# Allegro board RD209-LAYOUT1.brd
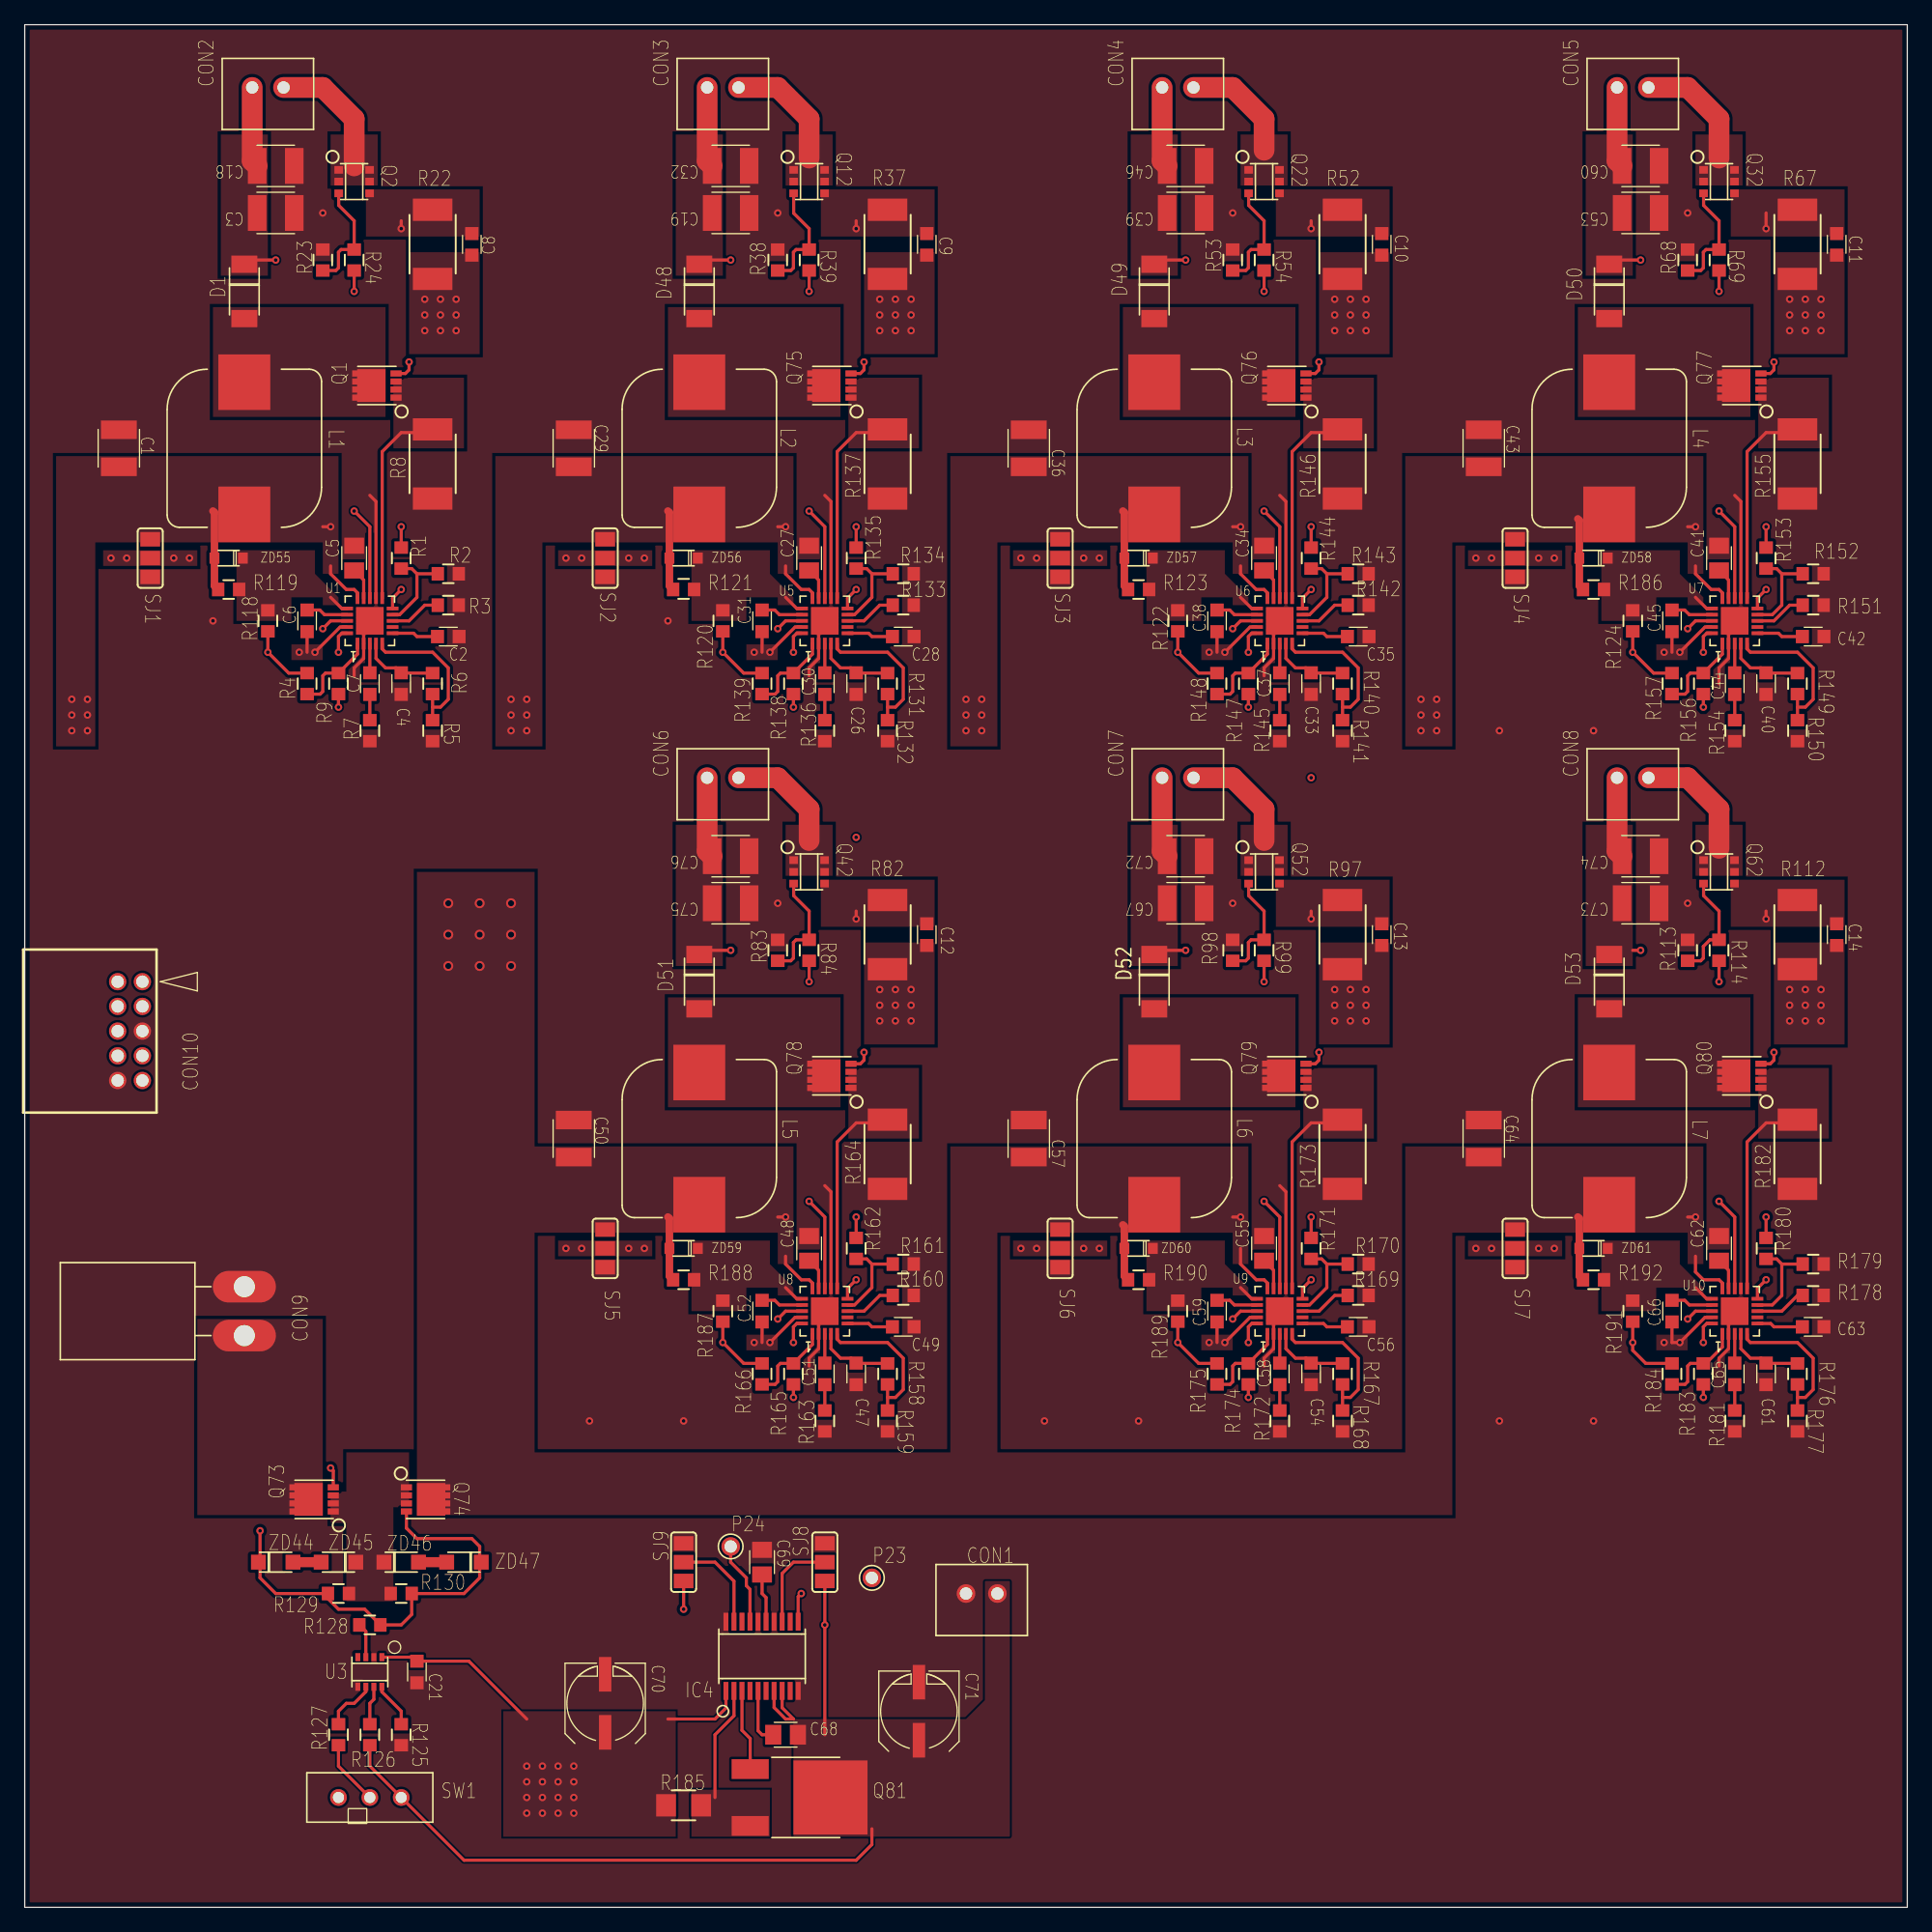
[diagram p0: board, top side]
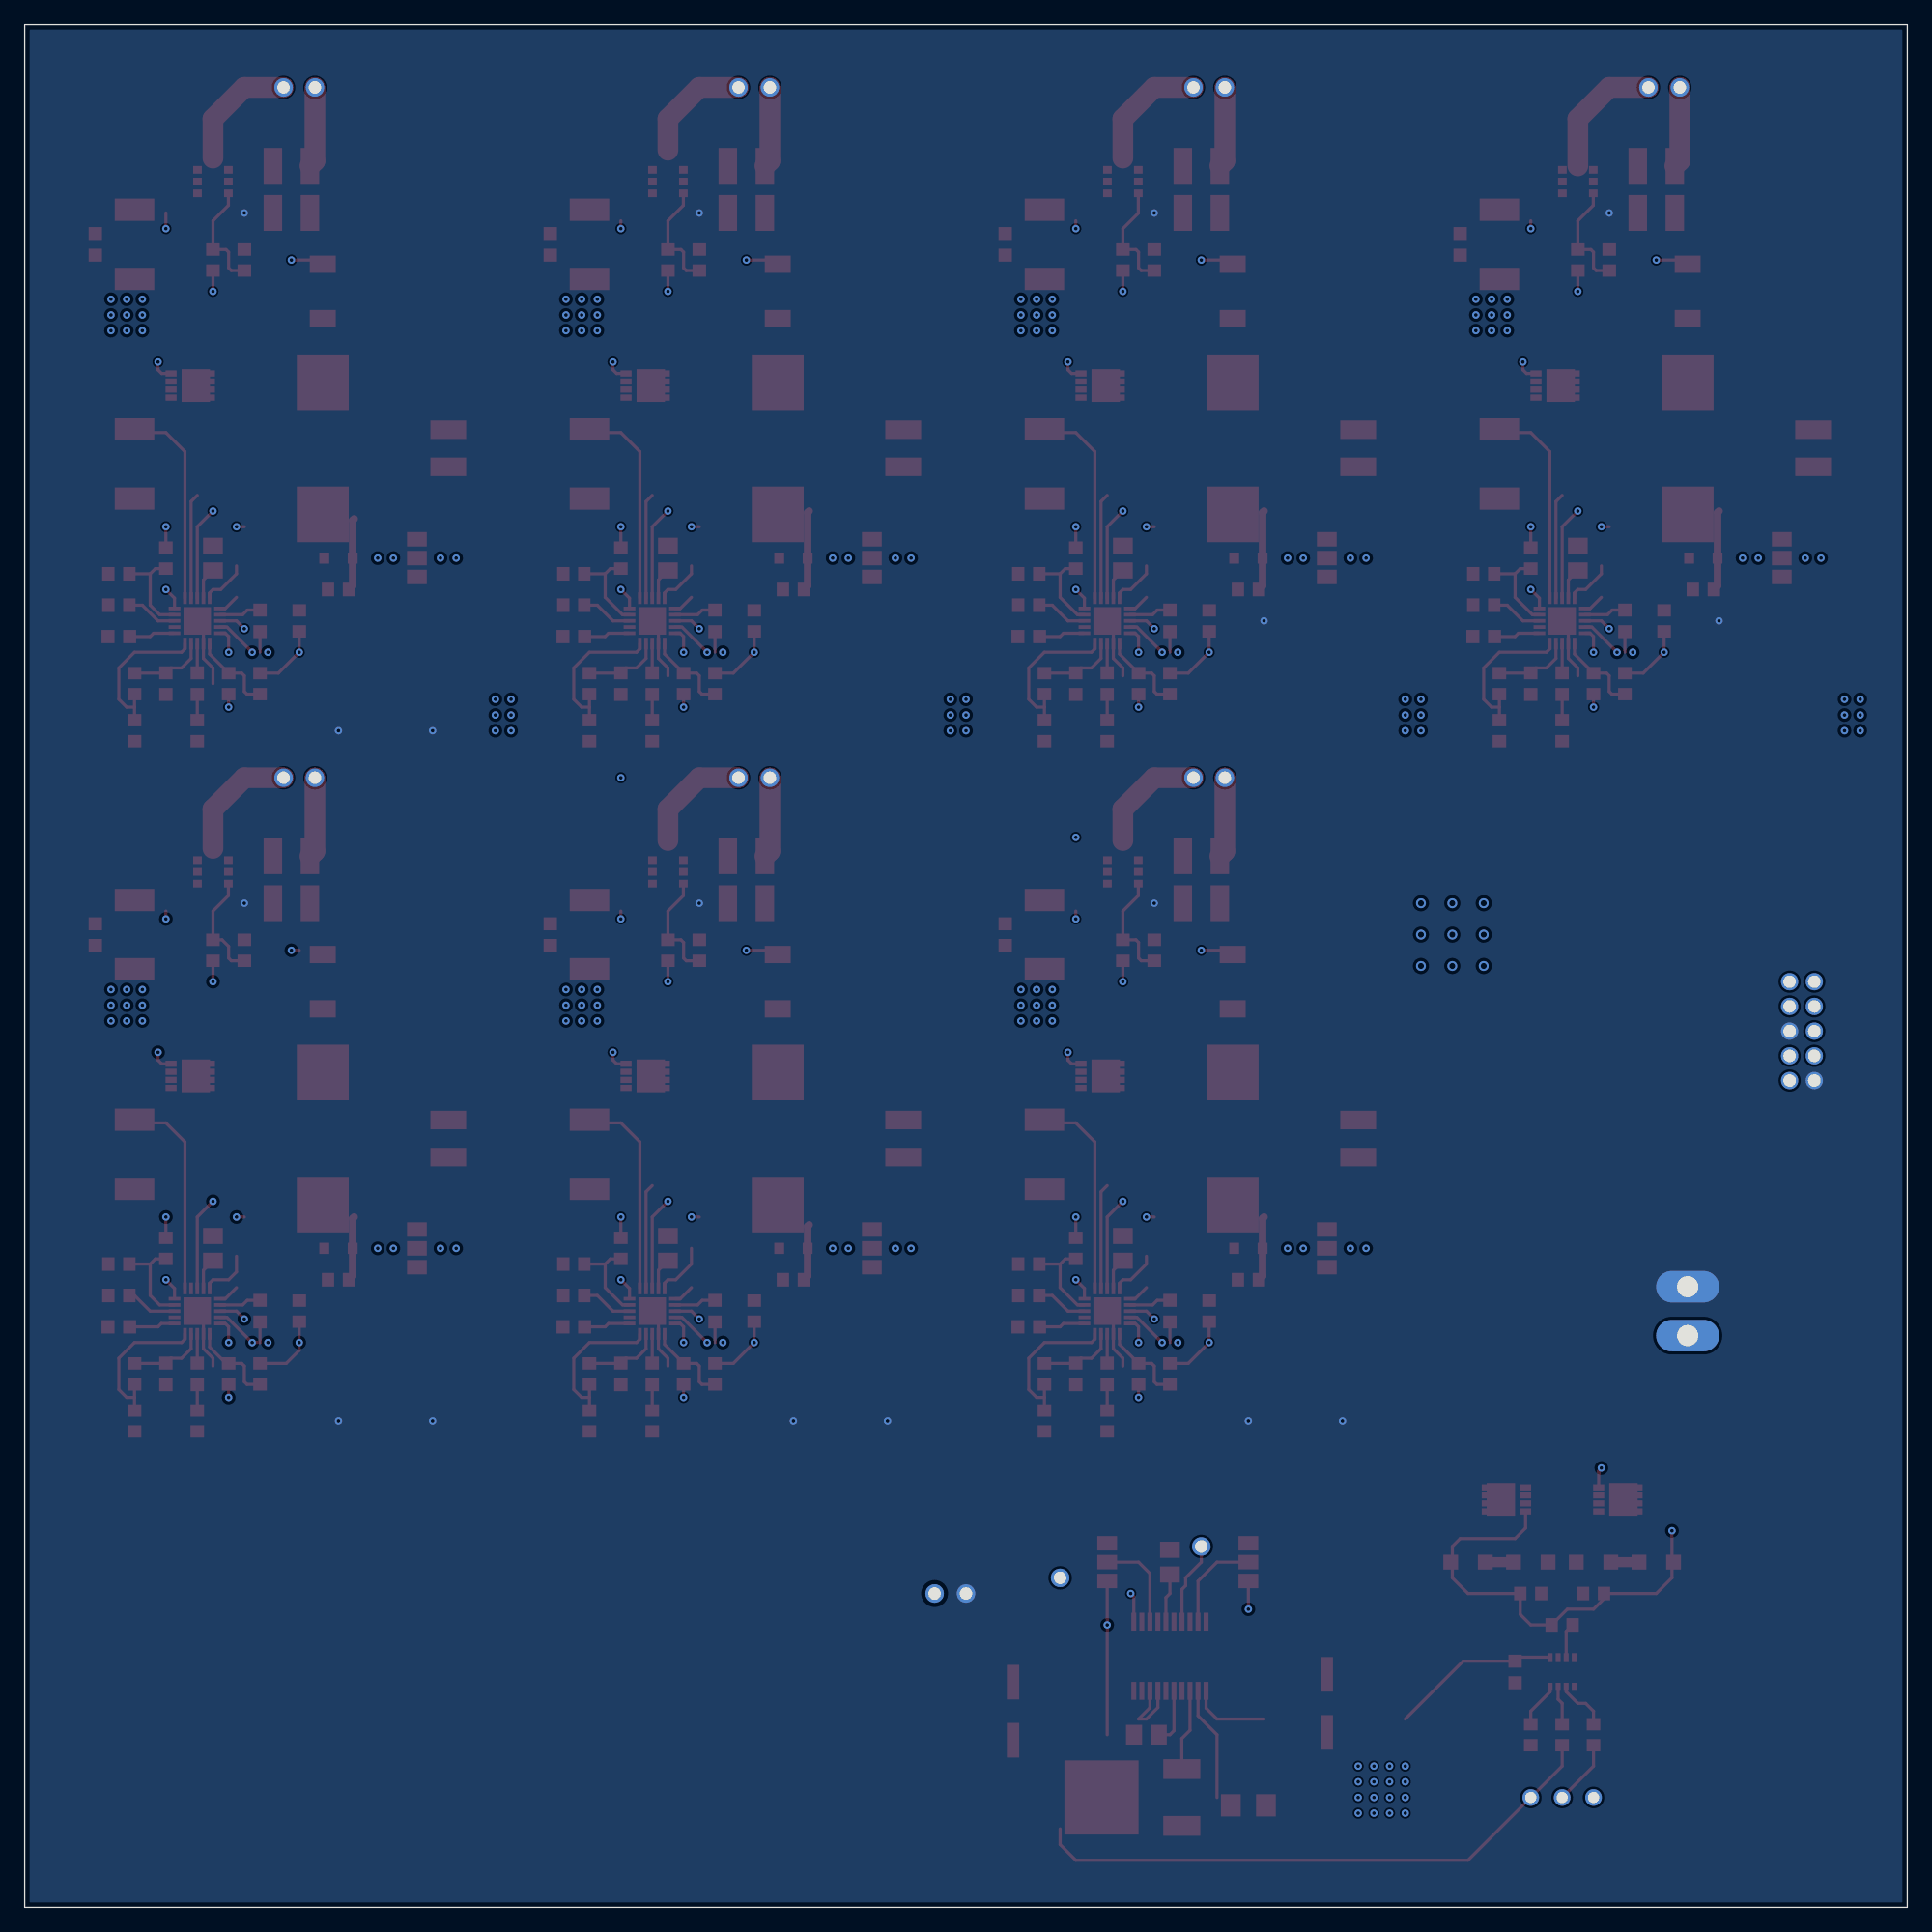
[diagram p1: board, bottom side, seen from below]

Outline 152.4 x 152.4 mm; copper layers: TOP, CONDUCTIVE2, CONDUCTIVE3, BOTTOM. Coordinates in mm from the lower left corner of the outline.
Outline path: rectangle 0,0 152.4,152.4

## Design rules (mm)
constraint set DEFAULT: 

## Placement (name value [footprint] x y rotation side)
C1  -  [C1210K]  7.62 118.11 270 top
C2  -  [C0603K]  34.29 102.87 180 top
C3  -  [C1210K]  20.32 137.16 180 top
C4  -  [C0603K]  30.48 99.06 90 top
C5  -  [C0805K]  26.67 109.22 270 top
C6  -  [C0603K]  22.86 104.14 90 top
C7  -  [C0603K]  27.94 99.06 90 top
C8  -  [C0603K]  36.2 134.62 90 top
C9  -  [C0603K]  73.02 134.62 90 top
C10  -  [C0603K]  109.85 134.62 90 top
C11  -  [C0603K]  146.69 134.62 90 top
C12  -  [C0603K]  73.02 78.74 90 top
C13  -  [C0603K]  109.85 78.74 90 top
C14  -  [C0603K]  146.69 78.74 90 top
C18  -  [C1210K]  20.32 140.97 180 top
C19  -  [C1210K]  57.15 137.16 180 top
C21  -  [C0603K]  31.75 19.05 270 top
C26  -  [C0603K]  67.31 99.06 90 top
C27  -  [C0805K]  63.5 109.22 270 top
C28  -  [C0603K]  71.12 102.87 180 top
C29  -  [C1210K]  44.45 118.11 270 top
C30  -  [C0603K]  64.77 99.06 90 top
C31  -  [C0603K]  59.69 104.14 90 top
C32  -  [C1210K]  57.15 140.97 180 top
C33  -  [C0603K]  104.14 99.06 90 top
C34  -  [C0805K]  100.33 109.22 270 top
C35  -  [C0603K]  107.95 102.87 180 top
C36  -  [C1210K]  81.28 118.11 270 top
C37  -  [C0603K]  101.6 99.06 90 top
C38  -  [C0603K]  96.52 104.14 90 top
C39  -  [C1210K]  93.98 137.16 180 top
C40  -  [C0603K]  140.97 99.06 90 top
C41  -  [C0805K]  137.16 109.22 270 top
C42  -  [C0603K]  144.78 102.87 180 top
C43  -  [C1210K]  118.11 118.11 270 top
C44  -  [C0603K]  138.43 99.06 90 top
C45  -  [C0603K]  133.35 104.14 90 top
C46  -  [C1210K]  93.98 140.97 180 top
C47  -  [C0603K]  67.31 43.18 90 top
C48  -  [C0805K]  63.5 53.34 270 top
C49  -  [C0603K]  71.12 46.99 180 top
C50  -  [C1210K]  44.45 62.23 270 top
C51  -  [C0603K]  64.77 43.18 90 top
C52  -  [C0603K]  59.69 48.26 90 top
C53  -  [C1210K]  130.81 137.16 180 top
C54  -  [C0603K]  104.14 43.18 90 top
C55  -  [C0805K]  100.33 53.34 270 top
C56  -  [C0603K]  107.95 46.99 180 top
C57  -  [C1210K]  81.28 62.23 270 top
C58  -  [C0603K]  101.6 43.18 90 top
C59  -  [C0603K]  96.52 48.26 90 top
C60  -  [C1210K]  130.81 140.97 180 top
C61  -  [C0603K]  140.97 43.18 90 top
C62  -  [C0805K]  137.16 53.34 270 top
C63  -  [C0603K]  144.78 46.99 180 top
C64  -  [C1210K]  118.11 62.23 270 top
C65  -  [C0603K]  138.43 43.18 90 top
C66  -  [C0603K]  133.35 48.26 90 top
C67  -  [C1210K]  93.98 81.28 180 top
C68  -  [C0805K]  61.6 13.97 180 top
C69  -  [C0805K]  59.69 27.94 90 top
C70  -  [UD_6_3X5_8_NICHICON]  46.99 16.51 270 top
C71  -  [UD_6_3X5_8_NICHICON]  72.39 15.88 270 top
C72  -  [C1210K]  93.98 85.09 180 top
C73  -  [C1210K]  130.81 81.28 180 top
C74  -  [C1210K]  130.81 85.09 180 top
C75  -  [C1210K]  57.15 81.28 180 top
C76  -  [C1210K]  57.15 85.09 180 top
CON1  -  [B2B_XH_A]  77.47 25.4 180 top
CON2  -  [B2B_XH_A]  19.68 147.32 180 top
CON3  -  [B2B_XH_A]  56.52 147.32 180 top
CON4  -  [B2B_XH_A]  93.34 147.32 180 top
CON5  -  [B2B_XH_A]  130.18 147.32 180 top
CON6  -  [B2B_XH_A]  56.52 91.44 180 top
CON7  -  [B2B_XH_A]  93.34 91.44 180 top
CON8  -  [B2B_XH_A]  130.18 91.44 180 top
CON9  -  [B2PS_VH]  17.78 48.26 90 top
CON10  -  [CTK03280ATP]  9.53 74.93 270 top
D1  -  [M_FLAT]  17.78 130.81 90 top
D48  -  [M_FLAT]  54.61 130.81 90 top
D49  -  [M_FLAT]  91.44 130.81 90 top
D50  -  [M_FLAT]  128.27 130.81 90 top
D51  -  [M_FLAT]  54.61 74.93 90 top
D52  -  [M_FLAT]  91.44 74.93 90 top
D53  -  [M_FLAT]  128.27 74.93 90 top
IC4  -  [TB9005FNG]  59.69 20.32 0 top
L1  -  [CLF12577NI_D]  17.78 118.11 90 top
L2  -  [CLF12577NI_D]  54.61 118.11 90 top
L3  -  [CLF12577NI_D]  91.44 118.11 90 top
L4  -  [CLF12577NI_D]  128.27 118.11 90 top
L5  -  [CLF12577NI_D]  54.61 62.23 90 top
L6  -  [CLF12577NI_D]  91.44 62.23 90 top
L7  -  [CLF12577NI_D]  128.27 62.23 90 top
P23  -  [CT]  68.58 26.67 270 top
P24  -  [CT]  57.15 29.21 270 top
Q1  -  [TSON_ADVANCE_WF_]  29.21 123.19 90 top
Q2  -  [TSOP6F]  26.67 139.7 270 top
Q12  -  [TSOP6F]  63.5 139.7 270 top
Q22  -  [TSOP6F]  100.33 139.7 270 top
Q32  -  [TSOP6F]  137.16 139.7 270 top
Q42  -  [TSOP6F]  63.5 83.82 270 top
Q52  -  [TSOP6F]  100.33 83.82 270 top
Q62  -  [TSOP6F]  137.16 83.82 270 top
Q73  -  [TSON_ADVANCE_WF_]  24.13 33.02 90 top
Q74  -  [TSON_ADVANCE_WF_]  31.75 33.02 270 top
Q75  -  [TSON_ADVANCE_WF_]  66.04 123.19 90 top
Q76  -  [TSON_ADVANCE_WF_]  102.87 123.19 90 top
Q77  -  [TSON_ADVANCE_WF_]  139.7 123.19 90 top
Q78  -  [TSON_ADVANCE_WF_]  66.04 67.31 90 top
Q79  -  [TSON_ADVANCE_WF_]  102.87 67.31 90 top
Q80  -  [TSON_ADVANCE_WF_]  139.7 67.31 90 top
Q81  -  [TTA005]  62.23 8.89 270 top
R1  -  [R0603]  30.48 109.22 90 top
R2  -  [R0603]  34.29 107.95 180 top
R3  -  [R0603]  34.29 105.41 0 top
R4  -  [R0603]  22.86 99.06 90 top
R5  -  [R0603]  33.02 95.25 270 top
R6  -  [R0603]  33.02 99.06 90 top
R7  -  [R0603]  27.94 95.25 90 top
R8  -  [R2512]  33.02 116.84 90 top
R9  -  [R0603]  25.4 99.06 90 top
R22  -  [R2512]  33.02 134.62 90 top
R23  -  [R0603]  24.13 133.35 270 top
R24  -  [R0603]  26.67 133.35 270 top
R37  -  [R2512]  69.85 134.62 90 top
R38  -  [R0603]  60.96 133.35 270 top
R39  -  [R0603]  63.5 133.35 270 top
R52  -  [R2512]  106.68 134.62 90 top
R53  -  [R0603]  97.79 133.35 270 top
R54  -  [R0603]  100.33 133.35 270 top
R67  -  [R2512]  143.51 134.62 90 top
R68  -  [R0603]  134.62 133.35 270 top
R69  -  [R0603]  137.16 133.35 270 top
R82  -  [R2512]  69.85 78.74 90 top
R83  -  [R0603]  60.96 77.47 270 top
R84  -  [R0603]  63.5 77.47 270 top
R97  -  [R2512]  106.68 78.74 90 top
R98  -  [R0603]  97.79 77.47 270 top
R99  -  [R0603]  100.33 77.47 270 top
R112  -  [R2512]  143.51 78.74 90 top
R113  -  [R0603]  134.62 77.47 270 top
R114  -  [R0603]  137.16 77.47 270 top
R118  -  [R0603]  19.68 104.14 270 top
R119  -  [R0603]  16.51 106.68 180 top
R120  -  [R0603]  56.52 104.14 270 top
R121  -  [R0603]  53.34 106.68 180 top
R122  -  [R0603]  93.34 104.14 270 top
R123  -  [R0603]  90.17 106.68 180 top
R124  -  [R0603]  130.18 104.14 270 top
R125  -  [R0603]  30.48 13.97 90 top
R126  -  [R0603]  27.94 13.97 270 top
R127  -  [R0603]  25.4 13.97 90 top
R128  -  [R0603]  27.94 22.86 0 top
R129  -  [R0603]  25.4 25.4 180 top
R130  -  [R0603]  30.48 25.4 180 top
R131  -  [R0603]  69.85 99.06 90 top
R132  -  [R0603]  69.85 95.25 270 top
R133  -  [R0603]  71.12 105.41 0 top
R134  -  [R0603]  71.12 107.95 180 top
R135  -  [R0603]  67.31 109.22 90 top
R136  -  [R0603]  64.77 95.25 90 top
R137  -  [R2512]  69.85 116.84 90 top
R138  -  [R0603]  62.23 99.06 90 top
R139  -  [R0603]  59.69 99.06 90 top
R140  -  [R0603]  106.68 99.06 90 top
R141  -  [R0603]  106.68 95.25 270 top
R142  -  [R0603]  107.95 105.41 0 top
R143  -  [R0603]  107.95 107.95 180 top
R144  -  [R0603]  104.14 109.22 90 top
R145  -  [R0603]  101.6 95.25 90 top
R146  -  [R2512]  106.68 116.84 90 top
R147  -  [R0603]  99.06 99.06 90 top
R148  -  [R0603]  96.52 99.06 90 top
R149  -  [R0603]  143.51 99.06 90 top
R150  -  [R0603]  143.51 95.25 270 top
R151  -  [R0603]  144.78 105.41 0 top
R152  -  [R0603]  144.78 107.95 180 top
R153  -  [R0603]  140.97 109.22 90 top
R154  -  [R0603]  138.43 95.25 90 top
R155  -  [R2512]  143.51 116.84 90 top
R156  -  [R0603]  135.89 99.06 90 top
R157  -  [R0603]  133.35 99.06 90 top
R158  -  [R0603]  69.85 43.18 90 top
R159  -  [R0603]  69.85 39.37 270 top
R160  -  [R0603]  71.12 49.53 0 top
R161  -  [R0603]  71.12 52.07 180 top
R162  -  [R0603]  67.31 53.34 90 top
R163  -  [R0603]  64.77 39.37 90 top
R164  -  [R2512]  69.85 60.96 90 top
R165  -  [R0603]  62.23 43.18 90 top
R166  -  [R0603]  59.69 43.18 90 top
R167  -  [R0603]  106.68 43.18 90 top
R168  -  [R0603]  106.68 39.37 270 top
R169  -  [R0603]  107.95 49.53 0 top
R170  -  [R0603]  107.95 52.07 180 top
R171  -  [R0603]  104.14 53.34 90 top
R172  -  [R0603]  101.6 39.37 90 top
R173  -  [R2512]  106.68 60.96 90 top
R174  -  [R0603]  99.06 43.18 90 top
R175  -  [R0603]  96.52 43.18 90 top
R176  -  [R0603]  143.51 43.18 90 top
R177  -  [R0603]  143.51 39.37 270 top
R178  -  [R0603]  144.78 49.53 0 top
R179  -  [R0603]  144.78 52.07 180 top
R180  -  [R0603]  140.97 53.34 90 top
R181  -  [R0603]  138.43 39.37 90 top
R182  -  [R2512]  143.51 60.96 90 top
R183  -  [R0603]  135.89 43.18 90 top
R184  -  [R0603]  133.35 43.18 90 top
R185  -  [R1206]  53.34 8.26 0 top
R186  -  [R0603]  127 106.68 180 top
R187  -  [R0603]  56.52 48.26 270 top
R188  -  [R0603]  53.34 50.8 180 top
R189  -  [R0603]  93.34 48.26 270 top
R190  -  [R0603]  90.17 50.8 180 top
R191  -  [R0603]  130.18 48.26 270 top
R192  -  [R0603]  127 50.8 180 top
SJ1  -  [SJ_2]  10.16 109.22 90 top
SJ2  -  [SJ_2]  46.99 109.22 90 top
SJ3  -  [SJ_2]  83.82 109.22 90 top
SJ4  -  [SJ_2]  120.65 109.22 90 top
SJ5  -  [SJ_2]  46.99 53.34 90 top
SJ6  -  [SJ_2]  83.82 53.34 90 top
SJ7  -  [SJ_2]  120.65 53.34 90 top
SJ8  -  [SJ_2]  64.77 27.94 90 top
SJ9  -  [SJ_2]  53.34 27.94 90 top
SW1  -  [SS_12SDP2]  27.94 8.89 90 top
U1  -  [20_TQFN]  27.94 104.14 0 top
U3  -  [PS_8]  27.94 19.05 180 top
U5  -  [20_TQFN]  64.77 104.14 0 top
U6  -  [20_TQFN]  101.6 104.14 0 top
U7  -  [20_TQFN]  138.43 104.14 0 top
U8  -  [20_TQFN]  64.77 48.26 0 top
U9  -  [20_TQFN]  101.6 48.26 0 top
U10  -  [20_TQFN]  138.43 48.26 0 top
ZD44  -  [ZD_16V]  20.32 27.94 180 top
ZD45  -  [ZD_16V]  25.4 27.94 0 top
ZD46  -  [ZD_16V]  30.48 27.94 180 top
ZD47  -  [ZD_16V]  35.56 27.94 0 top
ZD55  -  [USC]  16.51 109.22 180 top
ZD56  -  [USC]  53.34 109.22 180 top
ZD57  -  [USC]  90.17 109.22 180 top
ZD58  -  [USC]  127 109.22 180 top
ZD59  -  [USC]  53.34 53.34 180 top
ZD60  -  [USC]  90.17 53.34 180 top
ZD61  -  [USC]  127 53.34 180 top

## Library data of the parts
C1 C3 C18 C19 C29 C32 C36 C39 C43 C46 C50 C53 C57 C60 C64 C67 C72-C76 = C1210K: alternate symbols: (T:C1210K;B:C1210K_bk)
C2 C28 C35 C42 C49 C56 C63 = C0603K_1: alternate symbols: (T:C0603K;B:C0603K_bk)
C4 C6 C26 C31 C33 C38 C40 C45 C47 C52 C54 C59 C61 C66 = C0603K_3: alternate symbols: (T:C0603K;B:C0603K_bk)
C5 C27 C34 C41 C48 C55 C62 = C0805K_1: alternate symbols: (T:C0805K;B:C0805K_bk)
C7 C30 C37 C44 C51 C58 C65 = C0603K_4: alternate symbols: (T:C0603K;B:C0603K_bk)
C8-C14 = C0603K: alternate symbols: (T:C0603K;B:C0603K_bk)
C21 = C0603K_2: alternate symbols: (T:C0603K;B:C0603K_bk)
C68 = C0805K_2: alternate symbols: (T:C0805K;B:C0805K_bk)
C69 = C0805K_3: alternate symbols: (T:C0805K;B:C0805K_bk)
C70 C71 = UD-6_3X5_8_NICHICON: alternate symbols: (T:UD_6_3X5_8_NICHICON;B:UD_6_3X5_8_NICHICON__1)
CON1-CON8 = B2B-XH-A: alternate symbols: (T:B2B_XH_A;B:B2B_XH_A_bk)
CON9 = B2PS-VH: alternate symbols: (T:B2PS_VH;B:B2PS_VH_bk)
CON10 = GDM220002192: alternate symbols: (T:CTK03280ATP;B:CTK03280BTP)
D1 D48-D53 = M-FLAT: alternate symbols: (T:M_FLAT;B:M_FLAT_bk)
IC4 = TB9005FNG: alternate symbols: (T:TB9005FNG;B:TB9005FNG_bk)
L1-L7 = CLF12577NI-D: alternate symbols: (T:CLF12577NI_D;B:CLF12577NI_D_bk)
P23 P24 = CT: alternate symbols: (T:CT;B:CT_bk)
Q1 Q75-Q80 = TSON_ADVANCE_WF_1: alternate symbols: (T:TSON_ADVANCE_WF_;B:TSON_ADVANCE_WF_bk)
Q2 Q12 Q22 Q32 Q42 Q52 Q62 = TSOP6F: alternate symbols: (T:TSOP6F;B:TSOP6F_bk)
Q73 Q74 = TSON_ADVANCE_WF_2: alternate symbols: (T:TSON_ADVANCE_WF_;B:TSON_ADVANCE_WF_bk)
Q81 = TTA005: alternate symbols: (T:TTA005;B:TTA005_bk)
R1 R135 R144 R153 R162 R171 R180 = R0603_1: alternate symbols: (T:R0603;B:R0603_bk)
R2 R9 R126 R127 R134 R138 R143 R147 R152 R156 R161 R165 R170 R174 R179 R183 = R0603_6: alternate symbols: (T:R0603;B:R0603_bk)
R3 R133 R142 R151 R160 R169 R178 = R0603_8: alternate symbols: (T:R0603;B:R0603_bk)
R4 R139 R148 R157 R166 R175 R184 = R0603_9: alternate symbols: (T:R0603;B:R0603_bk)
R5 R132 R141 R150 R159 R168 R177 = R0603_10: alternate symbols: (T:R0603;B:R0603_bk)
R6 R131 R140 R149 R158 R167 R176 = R0603_11: alternate symbols: (T:R0603;B:R0603_bk)
R7 R136 R145 R154 R163 R172 R181 = R0603_12: alternate symbols: (T:R0603;B:R0603_bk)
R8 R22 R37 R52 R67 R82 R97 R112 R137 R146 R155 R164 R173 R182 = R2512: alternate symbols: (T:R2512;B:R2512_bk)
R23 R38 R53 R68 R83 R98 R113 R119 R121 R123 R186 R188 R190 R192 = R0603: alternate symbols: (T:R0603;B:R0603_bk)
R24 R39 R54 R69 R84 R99 R114 = R0603_7: alternate symbols: (T:R0603;B:R0603_bk)
R118 R120 R122 R124 R187 R189 R191 = R0603_2: alternate symbols: (T:R0603;B:R0603_bk)
R125 = R0603_3: alternate symbols: (T:R0603;B:R0603_bk)
R128 = R0603_4: alternate symbols: (T:R0603;B:R0603_bk)
R129 R130 = R0603_5: alternate symbols: (T:R0603;B:R0603_bk)
R185 = R1206: alternate symbols: (T:R1206;B:R1206_bk)
SJ1-SJ9 = SJ_2: alternate symbols: (T:SJ_2;B:SJ_2_bk)
SW1 = SS-12SDP2: alternate symbols: (T:SS_12SDP2;B:SS_12SDP2_bk)
U1 U5-U10 = 20-TQFN: alternate symbols: (T:20_TQFN;B:20_TQFN_bk)
U3 = PS-8: alternate symbols: (T:PS_8;B:PS_8_bk)
ZD44-ZD47 = ZD-16V: alternate symbols: (T:ZD_16V;B:ZD_16V_bk)
ZD55-ZD61 = USC: alternate symbols: (T:USC;B:USC_bk)

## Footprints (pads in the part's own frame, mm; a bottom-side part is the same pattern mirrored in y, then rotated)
20_TQFN
  rect 0.3x0.95 smd: 1(-1,-1.84) 2(-0.5,-1.84) 3(0,-1.84) 4(0.5,-1.84) 5(1,-1.84) 11(1,1.84) 12(0.5,1.84) 13(0,1.84) 14(-0.5,1.84) 15(-1,1.84)
  rect 0.95x0.3 smd: 6(1.84,-1) 7(1.84,-0.5) 8(1.84,0) 9(1.84,0.5) 10(1.84,1) 16(-1.84,1) 17(-1.84,0.5) 18(-1.84,0) 19(-1.84,-0.5) 20(-1.84,-1)
  rect 2.23x2.23 smd: EP(0,0)
B2B_XH_A
  round 1.5 hole 1: 1(-1.27,0) 2(1.27,0)
B2PS_VH
  oval 2.55x5.1 hole 1.7: P_1(-1.98,0) P_2(1.98,0)
C0603K
  rect 1.05x1.08 smd: 1(-0.875,0) 2(0.875,0)
C0805K
  rect 1.3x1.6 smd: 1(-1,0) 2(1,0)
C1210K
  rect 1.5x2.9 smd: 1(-1.5,0) 2(1.5,0)
CLF12577NI_D
  rect 4.5x4.2 smd: 1(-5.35,0) 2(5.35,0)
CT
  round 1.5 hole 1: P_1(0,0)
CTK03280ATP
  round 1.397 hole 1: 1(0,0) 2(0,-2) 3(2,0) 4(2,-2) 5(4,0) 6(4,-2) 7(6,0) 8(6,-2) 9(8,0) 10(8,-2)
M_FLAT
  rect 1.4x2.1 smd: A(-2.2,0) C(2.2,0)
PS_8
  rect 0.4x0.65 smd: 1(-0.975,-1.2) 2(-0.325,-1.2) 3(0.325,-1.2) 4(0.975,-1.2) 5(0.975,1.2) 6(0.325,1.2) 7(-0.325,1.2) 8(-0.975,1.2)
R0603
  rect 1x1.1 smd: 1(-0.85,0) 2(0.85,0)
R1206
  rect 1.6x1.803 smd: 1(-1.422,0) 2(1.422,0)
R2512
  rect 1.8x3.2 smd: 1(-2.8,0) 2(2.8,0)
SJ_2
  rect 1.168x1.6 smd: 1(-1.524,0) 2(0,0) 3(1.524,0)
SS_12SDP2
  round 1.35 hole 0.9: 1(0,2.54) 2(0,0) 3(0,-2.54)
TB9005FNG
  rect 0.4x1.45 smd: 1(-2.925,-2.8) 2(-2.275,-2.8) 3(-1.625,-2.8) 4(-0.975,-2.8) 5(-0.325,-2.8) 6(0.325,-2.8) 7(0.975,-2.8) 8(1.625,-2.8) 9(2.275,-2.8) 10(2.925,-2.8) 11(2.925,2.8) 12(2.275,2.8) 13(1.625,2.8) 14(0.975,2.8) 15(0.325,2.8) 16(-0.325,2.8) 17(-0.975,2.8) 18(-1.625,2.8) 19(-2.275,2.8) 20(-2.925,2.8)
TSON_ADVANCE_WF_
  rect 0.5x0.9 smd: 1(-0.975,-0.85) 2(-0.325,-0.85) 3(0.325,-0.85) 4(0.975,-0.85) 5(0.975,2.25) 6(0.325,2.25) 7(-0.325,2.25) 8(-0.975,2.25)
  rect 2.65x2.3 smd: EP(0,1.15)
TSOP6F
  rect 0.62x0.7 smd: 1(-0.95,-1.25) 2(0,-1.25) 3(0.95,-1.25) 4(0.95,1.25) 5(0,1.25) 6(-0.95,1.25)
TTA005
  rect 1.6x3 smd: B(-2.3,-3.5) E(2.3,-3.5)
  rect 6x6 smd: C(0,3)
UD_6_3X5_8_NICHICON
  rect 2.8x1 smd: 1(2.35,0) 2(-2.35,0)
USC
  rect 0.8x0.9 smd: A(1.15,0) K(-1.15,0)
ZD_16V
  rect 1.2x1.2 smd: A(-1.4,0) C(1.4,0)

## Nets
+5V: C68.1 C71.1 CON1.1 IC4.7 IC4.8 Q81.C R126.2 SJ8.1 SJ9.1 SW1.3
+12V: C21.1 C70.1 CON9.P_1 IC4.1 Q73.5 Q73.6 Q73.7 Q73.8 Q73.EP R185.1 U3.1
GND: C1.1 C2.1 C3.1 C4.1 C5.1 C18.1 C19.1 C21.2 C26.1 C27.1 C28.1 C29.1 C32.1 C33.1 C34.1 C35.1 C36.1 C39.1 C40.1 C41.1 C42.1 C43.1 C46.1 C47.1 C48.1 C49.1 C50.1 C53.1 C54.1 C55.1 C56.1 C57.1 C60.1 C61.1 C62.1 C63.1 C64.1 C67.1 C69.2 C70.2 C71.2 C72.1 C73.1 C74.1 C75.1 C76.1 CON1.2 CON9.P_2 CON10.5 CON10.10 IC4.10 IC4.14 IC4.16 IC4.20 R2.1 R3.2 R5.2 R7.1 R8.1 R23.1 R38.1 R53.1 R68.1 R83.1 R98.1 R113.1 R125.1 R132.2 R133.2 R134.1 R136.1 R137.1 R141.2 R142.2 R143.1 R145.1 R146.1 R150.2 R151.2 R152.1 R154.1 R155.1 R159.2 R160.2 R161.1 R163.1 R164.1 R168.2 R169.2 R170.1 R172.1 R173.1 R177.2 R178.2 R179.1 R181.1 R182.1 SJ1.1 SJ2.1 SJ3.1 SJ4.1 SJ5.1 SJ6.1 SJ7.1 SJ8.3 SJ9.3 U1.2 U1.12 U1.EP U3.2 U3.5 U5.2 U5.12 U5.EP U6.2 U6.12 U6.EP U7.2 U7.12 U7.EP U8.2 U8.12 U8.EP U9.2 U9.12 U9.EP U10.2 U10.12 U10.EP
VCC: C1.2 C29.2 C36.2 C43.2 C50.2 C57.2 C64.2 L1.1 L2.1 L3.1 L4.1 L5.1 L6.1 L7.1 Q74.5 Q74.6 Q74.7 Q74.8 Q74.EP R1.2 R119.2 R121.2 R123.2 R135.2 R144.2 R153.2 R162.2 R171.2 R180.2 R186.2 R188.2 R190.2 R192.2 SJ1.3 SJ2.3 SJ3.3 SJ4.3 SJ5.3 SJ6.3 SJ7.3 U1.15 U5.15 U6.15 U7.15 U8.15 U9.15 U10.15 ZD55.A ZD56.A ZD57.A ZD58.A ZD59.A ZD60.A ZD61.A
VDD_7104_DIAG: R126.1 U3.7
LED+1: C3.2 C18.2 CON2.2 D1.C R4.2 R118.2
LED+2: C19.2 C32.2 CON3.2 D48.C R120.2 R139.2
LED+3: C39.2 C46.2 CON4.2 D49.C R122.2 R148.2
LED+4: C53.2 C60.2 CON5.2 D50.C R124.2 R157.2
LED+5: C75.2 C76.2 CON6.2 D51.C R166.2 R187.2
LED+6: C67.2 C72.2 CON7.2 D52.C R175.2 R189.2
LED+7: C73.2 C74.2 CON8.2 D53.C R184.2 R191.2
LED-1: CON2.1 Q2.1 Q2.2 Q2.5 Q2.6
LED-2: CON3.1 Q12.1 Q12.2 Q12.5 Q12.6
LED-3: CON4.1 Q22.1 Q22.2 Q22.5 Q22.6
LED-4: CON5.1 Q32.1 Q32.2 Q32.5 Q32.6
LED-5: CON6.1 Q42.1 Q42.2 Q42.5 Q42.6
LED-6: CON7.1 Q52.1 Q52.2 Q52.5 Q52.6
LED-7: CON8.1 Q62.1 Q62.2 Q62.5 Q62.6
LV1: C6.1 C8.1 R9.1 R22.1 SJ1.2 U1.19
LV2: C9.1 C31.1 R37.1 R138.1 SJ2.2 U5.19
LV3: C10.1 C38.1 R52.1 R147.1 SJ3.2 U6.19
LV4: C11.1 C45.1 R67.1 R156.1 SJ4.2 U7.19
LV5: C12.1 C52.1 R82.1 R165.1 SJ5.2 U8.19
LV6: C13.1 C59.1 R97.1 R174.1 SJ6.2 U9.19
LV7: C14.1 C66.1 R112.1 R183.1 SJ7.2 U10.19
N_1: R5.1 R6.1 R131.1 R132.1 R140.1 R141.1 R149.1 R150.1 R158.1 R159.1 R167.1 R168.1 R176.1 R177.1 U1.5 U5.5 U6.5 U7.5 U8.5 U9.5 U10.5
N_2: C4.2 R6.2 U1.4
N_3: C5.2 U1.14
N_4: R3.1 U1.8
N_5: C2.2 U1.6
N_6: R1.1 R2.2 U1.9
N_7: Q1.4 U1.13
N_8: D1.A L1.2 Q1.5 Q1.6 Q1.7 Q1.8 Q1.EP
N_9: Q1.1 Q1.2 Q1.3 R8.2 U1.11
N_10: C7.1 C7.2 R7.2 U1.3
N_12: R4.1 R9.2 U1.1
N_13: C6.2 U1.17
N_14: Q73.4 Q74.4 R128.1 R128.2 R129.2 R130.1 U3.3 ZD44.A ZD44.C ZD45.A ZD46.A ZD47.A ZD47.C
N_15: Q2.3 R23.2 R24.1 R24.2 U1.18
N_16: C26.2 R131.2 U5.4
N_18: C33.2 R140.2 U6.4
N_19: C40.2 R149.2 U7.4
N_20: C47.2 R158.2 U8.4
N_21: C61.2 R176.2 U10.4
N_22: C54.2 R167.2 U9.4
N_54: IC4.2 Q81.E R185.2
N_55: Q12.3 R38.2 R39.1 R39.2 U5.18
N_75: C68.2 IC4.5
N_76: Q22.3 R53.2 R54.1 R54.2 U6.18
N_77: IC4.3 Q81.B
N_96: C69.1 IC4.15
N_97: Q32.3 R68.2 R69.1 R69.2 U7.18
N_117: IC4.13 SJ8.2
N_118: Q42.3 R83.2 R84.1 R84.2 U8.18
N_138: IC4.19 SJ9.2
N_139: Q52.3 R98.2 R99.1 R99.2 U9.18
N_159: C14.2 Q62.4 R112.2 U10.20
N_160: Q62.3 R113.2 R114.1 R114.2 U10.18
N_208: R120.1 R121.1 U5.16 ZD56.K
N_209: C13.2 Q52.4 R97.2 U9.20
N_214: C9.2 Q12.4 R37.2 U5.20
N_217: C12.2 Q42.4 R82.2 U8.20
N_218: C10.2 Q22.4 R52.2 U6.20
N_219: R122.1 R123.1 U6.16 ZD57.K
N_220: C8.2 Q2.4 R22.2 U1.20
N_221: R118.1 R119.1 U1.16 ZD55.K
N_222: R124.1 R186.1 U7.16 ZD58.K
N_223: R187.1 R188.1 U8.16 ZD59.K
N_224: R189.1 R190.1 U9.16 ZD60.K
N_225: R191.1 R192.1 U10.16 ZD61.K
N_231: R125.2 U3.8
N_232: R127.1 R127.2 SW1.2 U3.6
N_235: Q73.1 Q73.2 Q73.3 Q74.1 Q74.2 Q74.3 R129.1 R130.2 ZD45.C ZD46.C
N_243: IC4.11 P23.P_1
N_244: IC4.17 P24.P_1
N_251: C27.2 U5.14
N_252: R133.1 U5.8
N_253: C28.2 U5.6
N_254: R134.2 R135.1 U5.9
N_255: Q75.4 U5.13
N_256: D48.A L2.2 Q75.5 Q75.6 Q75.7 Q75.8 Q75.EP
N_257: Q75.1 Q75.2 Q75.3 R137.2 U5.11
N_258: C30.1 C30.2 R136.2 U5.3
N_260: C31.2 U5.17
N_261: R138.2 R139.1 U5.1
N_266: C34.2 U6.14
N_267: R142.1 U6.8
N_268: C35.2 U6.6
N_269: R143.2 R144.1 U6.9
N_270: Q76.4 U6.13
N_271: D49.A L3.2 Q76.5 Q76.6 Q76.7 Q76.8 Q76.EP
N_272: Q76.1 Q76.2 Q76.3 R146.2 U6.11
N_273: C37.1 C37.2 R145.2 U6.3
N_275: C38.2 U6.17
N_276: R147.2 R148.1 U6.1
N_281: C41.2 U7.14
N_282: R151.1 U7.8
N_283: C42.2 U7.6
N_284: R152.2 R153.1 U7.9
N_285: Q77.4 U7.13
N_286: D50.A L4.2 Q77.5 Q77.6 Q77.7 Q77.8 Q77.EP
N_287: Q77.1 Q77.2 Q77.3 R155.2 U7.11
N_288: C44.1 C44.2 R154.2 U7.3
N_290: C45.2 U7.17
N_291: R156.2 R157.1 U7.1
N_292: C11.2 Q32.4 R67.2 U7.20
N_296: C48.2 U8.14
N_297: R160.1 U8.8
N_298: C49.2 U8.6
N_299: R161.2 R162.1 U8.9
N_300: Q78.4 U8.13
N_301: D51.A L5.2 Q78.5 Q78.6 Q78.7 Q78.8 Q78.EP
N_302: Q78.1 Q78.2 Q78.3 R164.2 U8.11
N_303: C51.1 C51.2 R163.2 U8.3
N_305: C52.2 U8.17
N_306: R165.2 R166.1 U8.1
N_311: C55.2 U9.14
N_312: R169.1 U9.8
N_313: C56.2 U9.6
N_314: R170.2 R171.1 U9.9
N_315: Q79.4 U9.13
N_316: D52.A L6.2 Q79.5 Q79.6 Q79.7 Q79.8 Q79.EP
N_317: Q79.1 Q79.2 Q79.3 R173.2 U9.11
N_318: C58.1 C58.2 R172.2 U9.3
N_320: C59.2 U9.17
N_321: R174.2 R175.1 U9.1
N_326: C62.2 U10.14
N_327: R178.1 U10.8
N_328: C63.2 U10.6
N_329: R179.2 R180.1 U10.9
N_330: Q80.4 U10.13
N_331: D53.A L7.2 Q80.5 Q80.6 Q80.7 Q80.8 Q80.EP
N_332: Q80.1 Q80.2 Q80.3 R182.2 U10.11
N_333: C65.1 C65.2 R181.2 U10.3
N_335: C66.2 U10.17
N_336: R183.2 R184.1 U10.1
PWMDIM1: CON10.1 U1.10
PWMDIM2: CON10.6 U5.10
PWMDIM3: CON10.2 U6.10
PWMDIM4: CON10.7 U7.10
PWMDIM5: CON10.3 U8.10
PWMDIM6: CON10.8 U9.10
PWMDIM7: CON10.4 U10.10

Pads without a net: CON10 9; IC4 4 6 9 12 18; SW1 1; U1 7; U3 4; U5 7; U6 7; U7 7; U8 7; U9 7; U10 7

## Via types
v1: diameter 0.6, hole 0.3, TOP to BOTTOM, 253 vias
v2: diameter 0.8, hole 0.5, TOP to BOTTOM, 9 vias

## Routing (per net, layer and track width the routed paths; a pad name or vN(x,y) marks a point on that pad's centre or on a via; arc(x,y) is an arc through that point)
+5V: length 79.9
  TOP w0.254: R126.2 27.94,11.43 SW1.3 35.56,3.81 67.31,3.81 68.58,5.08 68.58,6.35 ; 64.77,13.97 v1(64.77,22.86) SJ8.1 ; IC4.7 60.67,16.17 61.6,15.24 62.23,15.24 61.32,16.16 IC4.8 ; SJ9.1 v1(53.34,24.13)
  CONDUCTIVE2 w0.254: v1(53.34,24.13) 63.5,24.13 v1(64.77,22.86)
+12V: length 20.3
  TOP w0.254: 52.07,15.24 55.88,15.24 56.77,16.12 IC4.1 ; 28.91,20.25 31.43,20.25 C21.1 35.96,19.93 40.64,15.24
  vias: v1(40.64,11.43) v1(40.64,10.16) v1(40.64,8.89) v1(40.64,7.62) v1(41.91,11.43) v1(41.91,10.16) v1(41.91,8.89) v1(41.91,7.62) v1(43.18,11.43) v1(43.18,10.16) v1(43.18,8.89) v1(43.18,7.62) v1(44.45,11.43) v1(44.45,10.16) v1(44.45,8.89) v1(44.45,7.62)
GND: length 86.6
  TOP w0.254: U5.12 65.27,113.8 64.77,114.3 ; 26.67,99.69 26.67,100.33 27.44,101.1 U1.2 27.44,103.64 U1.EP ; 100.33,43.82 100.33,44.45 101.1,45.22 U9.2 101.1,47.76 U9.EP ; U6.12 102.1,113.8 101.6,114.3 ; 137.16,99.06 137.16,100.33 137.93,101.1 U7.2 137.93,103.64 U7.EP ; U8.12 65.27,57.92 64.77,58.42 ; U9.12 102.1,57.92 101.6,58.42 ; 27.94,114.3 28.44,113.8 U1.12 ; 138.43,114.3 138.93,113.8 U7.12 ; 63.5,99.69 63.5,100.33 64.27,101.1 U5.2 64.27,103.64 U5.EP ; 137.16,43.82 137.16,44.45 137.93,45.22 U10.2 137.93,47.76 U10.EP ; 63.5,43.82 63.5,44.45 64.27,45.22 U8.2 64.27,47.76 U8.EP ; 100.33,99.69 100.33,100.33 101.1,101.1 U6.2 101.1,103.64 U6.EP
  vias: v1(15.24,104.14) v1(24.13,137.16) v1(45.72,39.37) v1(52.07,104.14) v1(53.34,39.37) v1(60.96,137.16) v1(60.96,81.28) v1(82.55,39.37) v1(90.17,39.37) v1(97.79,137.16) v1(97.79,81.28) v1(119.38,95.25) v1(119.38,39.37) v1(127,95.25) v1(127,39.37) v1(134.62,137.16) v1(134.62,81.28)
VCC: length 125
  TOP w0.254: v1(98.42,111.76) 97.79,111.76 ; U1.15 26.94,106.41 26.67,106.68 26.04,106.68 24.77,107.95 24.77,108.58 ; U9.15 100.6,50.53 100.33,50.8 99.69,50.8 98.42,52.07 98.42,53.34 ; R171.2 v1(104.14,55.88) ; v1(61.6,111.76) 60.96,111.76 ; v1(135.26,55.88) 134.62,55.88 ; U6.15 100.6,106.41 100.33,106.68 99.69,106.68 98.42,107.95 98.42,108.58 ; R180.2 v1(140.97,55.88) ; R1.2 v1(30.48,111.76) ; 61.6,108.58 61.6,107.95 62.87,106.68 63.5,106.68 63.77,106.41 U5.15 ; 135.26,52.71 135.26,51.44 135.89,50.8 137.16,50.8 137.43,50.53 U10.15 ; R153.2 v1(140.97,111.76) ; U7.15 137.43,106.41 137.16,106.68 136.53,106.68 135.26,107.95 135.26,108.58 ; 61.6,52.71 61.6,52.07 62.87,50.8 63.5,50.8 63.77,50.53 U8.15 ; R162.2 v1(67.31,55.88) ; v1(98.42,55.88) 97.79,55.88 ; v1(135.26,111.76) 134.62,111.76 ; R144.2 v1(104.14,111.76) ; v1(24.77,111.76) 24.13,111.76 ; R135.2 v1(67.31,111.76) ; v1(61.6,55.88) 60.96,55.88
  TOP w0.61: R186.2 125.85,106.98 ZD58.A 125.85,112.27 125.73,112.39 ; 125.73,55.88 125.85,55.76 ZD61.A 125.85,51.1 R192.2 ; 88.9,55.25 89.02,55.12 ZD60.A 89.02,51.1 R190.2 ; R119.2 15.36,106.98 ZD55.A 15.36,112.91 15.24,113.03 ; R123.2 89.02,106.98 ZD57.A 89.02,112.91 88.9,113.03 ; 52.07,113.03 52.19,112.91 ZD56.A 52.19,106.98 R121.2 ; R188.2 52.19,51.1 ZD59.A 52.19,55.76 52.07,55.88
  CONDUCTIVE3 w0.254: v1(140.97,111.76) v1(135.26,111.76) ; v1(104.14,111.76) v1(98.42,111.76) ; v1(140.97,55.88) v1(135.26,55.88) ; v1(30.48,111.76) v1(24.77,111.76) ; v1(67.31,111.76) v1(61.6,111.76) ; v1(67.31,55.88) v1(61.6,55.88) ; v1(104.14,55.88) v1(98.42,55.88)
  vias: v1(3.81,97.79) v1(3.81,96.52) v1(3.81,95.25) v1(5.08,97.79) v1(5.08,96.52) v1(5.08,95.25) v1(39.37,97.79) v1(39.37,96.52) v1(39.37,95.25) v1(40.64,97.79) v1(40.64,96.52) v1(40.64,95.25) v1(76.2,97.79) v1(76.2,96.52) v1(76.2,95.25) v1(77.47,97.79) v1(77.47,96.52) v1(77.47,95.25) v1(113.03,97.79) v1(113.03,96.52) v1(113.03,95.25) v1(114.3,97.79) v1(114.3,96.52) v1(114.3,95.25) v2(34.29,81.28) v2(34.29,78.74) v2(34.29,76.2) v2(36.83,81.28) v2(36.83,78.74) v2(36.83,76.2) v2(39.37,81.28) v2(39.37,78.74) v2(39.37,76.2)
VDD_7104_DIAG: length 3.2
  TOP w0.254: R126.1 27.94,16.51 28.27,16.84 U3.7
LED+1: length 46.8
  TOP w0.254: v1(20.32,133.35) 18.12,133.35 D1.C ; R4.2 21.38,99.91 v1(19.68,101.6) R118.2
  TOP w1.676: C18.2 18.41,141.38 CON2.2
  CONDUCTIVE3 w0.254: v1(20.32,133.35) 20.32,102.23 v1(19.68,101.6)
LED+2: length 46.8
  TOP w0.254: D48.C 54.95,133.35 v1(57.15,133.35) ; R120.2 v1(56.52,101.6) 58.21,99.91 R139.2
  TOP w1.676: C32.2 55.25,141.38 55.25,147.32
  CONDUCTIVE3 w0.254: v1(56.52,101.6) 57.15,102.23 v1(57.15,133.35)
LED+3: length 46.8
  TOP w0.254: v1(93.98,133.35) 91.78,133.35 D49.C ; R122.2 v1(93.34,101.6) 95.03,99.91 R148.2
  TOP w1.676: C46.2 92.08,141.38 CON4.2
  CONDUCTIVE3 w0.254: v1(93.98,133.35) 93.98,102.23 v1(93.34,101.6)
LED+4: length 46.8
  TOP w0.254: v1(130.81,133.35) 128.61,133.35 D50.C ; R124.2 v1(130.18,101.6) 131.87,99.91 R157.2
  TOP w1.676: CON5.2 128.91,141.38 C60.2
  CONDUCTIVE3 w0.254: v1(130.18,101.6) 130.81,102.23 v1(130.81,133.35)
LED+5: length 46.8
  TOP w0.254: D51.C 54.95,77.47 v1(57.15,77.47) ; R187.2 v1(56.52,45.72) 58.21,44.03 R166.2
  TOP w1.676: 55.25,91.44 55.25,85.49 C76.2
  CONDUCTIVE3 w0.254: v1(57.15,77.47) 57.15,46.36 v1(56.52,45.72)
LED+6: length 46.8
  TOP w0.254: v1(93.98,77.47) 91.78,77.47 D52.C ; R175.2 95.03,44.03 v1(93.34,45.72) R189.2
  TOP w1.676: CON7.2 92.08,85.49 C72.2
  CONDUCTIVE3 w0.254: v1(93.98,77.47) 93.98,46.36 v1(93.34,45.72)
LED+7: length 45.1
  TOP w0.254: v1(130.81,77.47) 130.18,77.47 ; R191.2 v1(130.18,45.72) 130.18,45.09 131.23,44.03 R184.2
  TOP w1.676: C74.2 128.91,85.49 CON8.2
  CONDUCTIVE3 w0.254: v1(130.18,45.72) 130.81,46.36 v1(130.81,77.47)
LED-1: length 10.6
  TOP w1.676: CON2.1 24.13,147.32 26.67,144.78 26.67,140.97
LED-2: length 9.9
  TOP w1.676: CON3.1 60.96,147.32 63.5,144.78 63.5,141.61
LED-3: length 9.3
  TOP w1.676: CON4.1 97.79,147.32 100.33,144.78 100.33,142.24
LED-4: length 9.9
  TOP w1.676: 137.16,141.61 137.16,144.78 134.62,147.32 CON5.1
LED-5: length 9.3
  TOP w1.676: CON6.1 60.96,91.44 63.5,88.9 63.5,86.36
LED-6: length 9.3
  TOP w1.676: 100.33,86.36 100.33,88.9 97.79,91.44 CON7.1
LED-7: length 9.9
  TOP w1.676: CON8.1 134.62,91.44 137.16,88.9 137.16,85.72
LV1: length 8.1
  TOP w0.254: v1(23.5,101.6) 25.54,103.64 U1.19 ; C6.1 22.86,101.6 ; R9.1 v1(25.4,97.16)
  CONDUCTIVE2 w0.254: v1(25.4,97.16) 23.5,97.16
  vias: v1(6.98,109.22) v1(8.26,109.22) v1(12.06,109.22) v1(13.33,109.22) v1(22.22,101.6) v1(32.38,130.18) v1(32.38,128.91) v1(32.38,127.63) v1(33.66,130.18) v1(33.66,128.91) v1(33.66,127.63) v1(34.93,130.18) v1(34.93,128.91) v1(34.93,127.63)
LV2: length 8.1
  TOP w0.254: U5.19 62.37,103.64 v1(60.33,101.6) ; R138.1 v1(62.23,97.16) ; C31.1 59.69,101.6
  CONDUCTIVE2 w0.254: v1(62.23,97.16) 60.33,97.16
  vias: v1(43.82,109.22) v1(45.09,109.22) v1(48.9,109.22) v1(50.17,109.22) v1(59.05,101.6) v1(69.21,130.18) v1(69.21,128.91) v1(69.21,127.63) v1(70.48,130.18) v1(70.48,128.91) v1(70.48,127.63) v1(71.75,130.18) v1(71.75,128.91) v1(71.75,127.63)
LV3: length 8.1
  TOP w0.254: U6.19 99.19,103.64 v1(97.16,101.6) ; C38.1 96.52,101.6 ; R147.1 v1(99.06,97.16)
  CONDUCTIVE2 w0.254: v1(99.06,97.16) 97.16,97.16
  vias: v1(80.64,109.22) v1(81.91,109.22) v1(85.72,109.22) v1(86.99,109.22) v1(95.88,101.6) v1(106.05,130.18) v1(106.05,128.91) v1(106.05,127.63) v1(107.31,130.18) v1(107.31,128.91) v1(107.31,127.63) v1(108.58,130.18) v1(108.58,128.91) v1(108.58,127.63)
LV4: length 8.1
  TOP w0.254: v1(133.99,101.6) 136.03,103.64 U7.19 ; R156.1 v1(135.89,97.16) ; C45.1 133.35,101.6
  CONDUCTIVE2 w0.254: v1(135.89,97.16) 133.99,97.16
  vias: v1(117.47,109.22) v1(118.74,109.22) v1(122.55,109.22) v1(123.83,109.22) v1(132.72,101.6) v1(142.88,130.18) v1(142.88,128.91) v1(142.88,127.63) v1(144.15,130.18) v1(144.15,128.91) v1(144.15,127.63) v1(145.42,130.18) v1(145.42,128.91) v1(145.42,127.63)
LV5: length 8.1
  TOP w0.254: v1(60.33,45.72) 62.37,47.76 U8.19 ; C52.1 59.69,45.72 ; R165.1 v1(62.23,41.28)
  CONDUCTIVE2 w0.254: v1(62.23,41.28) 60.33,41.28
  vias: v1(43.82,53.34) v1(45.09,53.34) v1(48.9,53.34) v1(50.17,53.34) v1(59.05,45.72) v1(69.21,74.3) v1(69.21,73.02) v1(69.21,71.75) v1(70.48,74.3) v1(70.48,73.02) v1(70.48,71.75) v1(71.75,74.3) v1(71.75,73.02) v1(71.75,71.75)
LV6: length 8.1
  TOP w0.254: R174.1 v1(99.06,41.28) ; C59.1 96.52,45.72 ; U9.19 99.19,47.76 v1(97.16,45.72)
  CONDUCTIVE2 w0.254: v1(99.06,41.28) 97.16,41.28
  vias: v1(80.64,53.34) v1(81.91,53.34) v1(85.72,53.34) v1(86.99,53.34) v1(95.88,45.72) v1(106.05,74.3) v1(106.05,73.02) v1(106.05,71.75) v1(107.31,74.3) v1(107.31,73.02) v1(107.31,71.75) v1(108.58,74.3) v1(108.58,73.02) v1(108.58,71.75)
LV7: length 8.7
  TOP w0.254: U10.19 136.03,47.76 v1(133.99,45.72) 133.35,45.72 C66.1 ; R183.1 v1(135.89,41.28)
  CONDUCTIVE2 w0.254: v1(135.89,41.28) 133.99,41.28
  vias: v1(117.47,53.34) v1(118.74,53.34) v1(122.55,53.34) v1(123.83,53.34) v1(132.72,45.72) v1(142.88,74.3) v1(142.88,73.02) v1(142.88,71.75) v1(144.15,74.3) v1(144.15,73.02) v1(144.15,71.75) v1(145.42,74.3) v1(145.42,73.02) v1(145.42,71.75)
N_1: length 88.2
  TOP w0.254: 143.51,97.16 R150.1 ; 143.51,97.16 144.15,97.16 144.78,97.79 144.78,100.33 143.51,101.6 139.7,101.6 139.43,101.87 U7.5 ; 143.51,97.16 R149.1 ; 69.85,41.28 R159.1 ; 69.85,41.28 70.48,41.28 71.12,41.91 71.12,44.45 69.85,45.72 66.04,45.72 65.77,45.99 U8.5 ; 69.85,41.28 R158.1 ; U9.5 102.6,45.99 102.87,45.72 106.68,45.72 107.95,44.45 107.95,41.91 107.31,41.28 106.68,41.28 ; U1.5 28.94,101.87 29.21,101.6 33.02,101.6 34.29,100.33 34.29,97.79 33.66,97.16 33.02,97.16 ; 33.02,97.16 R5.1 ; 33.02,97.16 R6.1 ; U10.5 139.43,45.99 139.7,45.72 143.51,45.72 144.78,44.45 144.78,41.91 144.15,41.28 143.51,41.28 ; 106.68,41.28 R168.1 ; 106.68,41.28 R167.1 ; 143.51,41.28 R176.1 ; 143.51,41.28 R177.1 ; R140.1 106.68,97.16 ; 106.68,97.16 R141.1 ; 106.68,97.16 107.31,97.16 107.95,97.79 107.95,100.33 106.68,101.6 102.87,101.6 102.6,101.87 U6.5 ; 69.85,97.16 70.48,97.16 71.12,97.79 71.12,100.33 69.85,101.6 66.04,101.6 65.77,101.87 U5.5 ; 69.85,97.16 R131.1 ; 69.85,97.16 R132.1
N_2: length 6.3
  TOP w0.254: R6.2 30.48,99.91 ; U1.4 28.44,101.1 29.21,100.33 30.09,100.33 C4.2
N_3: length 2.6
  TOP w0.254: U1.14 27.44,107.45 C5.2
N_4: length 4.2
  TOP w0.254: U1.8 31.11,104.14 32.38,105.41 R3.1
N_5: length 3.7
  TOP w0.254: U1.6 31.48,103.14 31.75,102.87 C2.2
N_6: length 7.6
  TOP w0.254: 31.75,107.95 31.75,106.05 30.34,104.64 U1.9 ; 31.75,107.95 31.33,108.37 R1.1 ; 31.75,107.95 R2.2
N_7: length 23.3
  TOP w0.254: v1(31.11,125.09) 31.11,124.46 30.82,124.16 Q1.4 ; U1.13 27.94,111.76 v1(26.67,113.03)
  CONDUCTIVE3 w0.254: v1(31.11,125.09) 26.67,120.65 v1(26.67,113.03)
N_9: length 16.7
  TOP w0.254: U1.11 28.94,117.84 30.48,119.38 32.76,119.38 R8.2
N_10: length 4.5
  TOP w0.254: U1.3 C7.2 ; C7.1 R7.2
N_12: length 7
  TOP w0.254: U1.1 26.94,101.45 R9.2 24.34,99.91 24.13,99.69 24.13,98.42 23.91,98.21 R4.1
N_13: length 3.4
  TOP w0.254: U1.17 24.27,104.64 23.89,105.02 C6.2
N_14: length 55.1
  TOP w0.254: v1(19.05,30.48) 19.05,28.07 ; 19.05,28.07 19.05,26.67 20.32,25.4 R129.2 24.55,24.98 25.4,24.13 27.52,24.13 R128.2 30.48,22.86 31.33,23.71 R130.1 35.56,25.4 36.83,26.67 36.83,27.81 ZD47.C 36.83,28.07 36.83,29.21 36.2,29.84 31.75,29.84 30.9,30.7 Q74.4 ; 19.05,28.07 ZD44.C ; Q73.4 24.98,35.35 v1(24.77,35.56) ; 27.61,20.25 27.61,22.34 R128.1
  TOP w0.813: ZD46.A ZD47.A ; ZD44.A ZD45.A
  CONDUCTIVE3 w0.254: v1(24.77,35.56) 21.59,35.56 19.05,33.02 v1(19.05,30.48)
N_15: length 41.9
  TOP w0.254: Q2.3 25.42,137.78 26.67,136.53 R24.1 25.61,134.2 25.4,133.99 25.4,132.72 25.18,132.5 R23.2 ; v1(26.67,130.81) R24.2 ; U1.18 24.77,104.14 v1(24.13,103.5)
  CONDUCTIVE3 w0.254: v1(26.67,130.81) 23.5,127.63 23.5,104.14 v1(24.13,103.5)
N_16: length 6.3
  TOP w0.254: C26.2 66.91,100.33 66.04,100.33 65.27,101.1 U5.4 ; R131.2 67.31,99.91
N_18: length 6.3
  TOP w0.254: R140.2 104.14,99.91 ; C33.2 103.74,100.33 102.87,100.33 102.1,101.1 U6.4
N_19: length 6.3
  TOP w0.254: R149.2 140.97,99.91 ; C40.2 140.58,100.33 139.7,100.33 138.93,101.1 U7.4
N_20: length 6.3
  TOP w0.254: C47.2 66.91,44.45 66.04,44.45 65.27,45.22 U8.4 ; R158.2 67.31,44.03
N_21: length 6.3
  TOP w0.254: C61.2 140.58,44.45 139.7,44.45 138.93,45.22 U10.4 ; R176.2 140.97,44.03
N_22: length 6.3
  TOP w0.254: R167.2 104.14,44.03 ; C54.2 103.74,44.45 102.87,44.45 102.1,45.22 U9.4
N_54: length 9.3
  TOP w0.254: 55.88,8.89 55.88,13.97 57.42,15.5 IC4.2
N_55: length 41.9
  TOP w0.254: Q12.3 62.25,137.14 63.5,135.89 R39.1 62.45,134.2 62.23,133.99 62.23,132.72 62.02,132.5 R38.2 ; v1(60.96,103.5) 61.6,104.14 U5.18 ; v1(63.5,130.81) R39.2
  CONDUCTIVE3 w0.254: v1(63.5,130.81) 60.33,127.63 60.33,104.14 v1(60.96,103.5)
N_75: length 4.6
  TOP w0.254: IC4.5 59.37,14.29 59.69,13.97 C68.2
N_76: length 41.9
  TOP w0.254: v1(100.33,130.81) R54.2 ; U6.18 98.42,104.14 v1(97.79,103.5) ; Q22.3 99.08,137.78 100.33,136.53 R54.1 99.27,134.2 99.06,133.99 99.06,132.72 98.84,132.5 R53.2
  CONDUCTIVE3 w0.254: v1(97.79,103.5) 97.16,104.14 97.16,127.63 v1(100.33,130.81)
N_77: length 6.6
  TOP w0.254: Q81.B 58.73,13.66 58.07,14.32 IC4.3
N_96: length 4
  TOP w0.254: C69.1 59.69,25.4 60.02,25.07 60.02,23.12
N_97: length 41.9
  TOP w0.254: U7.18 135.26,104.14 v1(134.62,103.5) ; v1(137.16,130.81) R69.2 ; R68.2 135.68,132.5 135.89,132.72 135.89,133.99 136.11,134.2 R69.1 137.16,136.53 135.91,137.78 Q32.3
  CONDUCTIVE3 w0.254: v1(134.62,103.5) 133.99,104.14 133.99,127.63 v1(137.16,130.81)
N_117: length 7.7
  TOP w0.254: IC4.13 61.32,27.02 62.23,27.94 SJ8.2
N_118: length 41.9
  TOP w0.254: U8.18 61.6,48.26 v1(60.96,47.62) ; v1(63.5,74.93) R84.2 ; Q42.3 62.25,81.89 63.5,80.64 R84.1 62.45,78.32 62.23,78.1 62.23,76.83 62.02,76.62 R83.2
  CONDUCTIVE3 w0.254: v1(63.5,74.93) 60.33,71.75 60.33,48.26 v1(60.96,47.62)
N_138: length 8
  TOP w0.254: SJ9.2 55.88,27.94 57.42,26.41 IC4.19
N_139: length 41.9
  TOP w0.254: R98.2 98.84,76.62 99.06,76.83 99.06,78.1 99.27,78.32 R99.1 100.33,80.64 99.08,81.89 Q52.3 ; v1(97.79,47.62) 98.42,48.26 U9.18 ; v1(100.33,74.93) R99.2
  CONDUCTIVE3 w0.254: v1(100.33,74.93) 97.16,71.75 97.16,48.26 v1(97.79,47.62)
N_159: length 44
  TOP w0.254: v1(140.97,80.01) 140.97,80.64 ; U10.20 136.16,47.26 135.89,46.99 v1(135.89,45.72)
  CONDUCTIVE3 w0.254: v1(135.89,45.72) 141.61,45.72 142.88,46.99 142.88,70.48 140.97,72.39 v1(140.97,80.01)
N_160: length 41.7
  TOP w0.254: Q62.3 135.91,81.89 137.16,80.64 R114.1 136.42,78.32 135.89,77.79 135.89,76.83 135.68,76.62 R113.2 ; v1(137.16,74.93) R114.2 ; U10.18 135.26,48.26 v1(134.62,47.62)
  CONDUCTIVE3 w0.254: v1(137.16,74.93) 133.99,71.75 133.99,48.26 v1(134.62,47.62)
N_208: length 1.7
  TOP w0.254: U5.16 62.5,105.14 61.6,106.05
N_209: length 44
  TOP w0.254: U9.20 99.33,47.26 99.06,46.99 v1(99.06,45.72) ; v1(104.14,80.01) 104.14,80.64
  CONDUCTIVE3 w0.254: v1(104.14,80.01) 104.14,71.75 106.05,69.85 106.05,46.99 104.77,45.72 v1(99.06,45.72)
N_214: length 44
  TOP w0.254: U5.20 62.5,103.14 62.23,102.87 v1(62.23,101.6) ; v1(67.31,135.89) 67.31,136.53
  CONDUCTIVE3 w0.254: v1(67.31,135.89) 67.31,127.63 69.21,125.73 69.21,102.87 67.94,101.6 v1(62.23,101.6)
N_217: length 44
  TOP w0.254: v1(67.31,80.01) 67.31,80.64 ; U8.20 62.5,47.26 62.23,46.99 v1(62.23,45.72)
  CONDUCTIVE3 w0.254: v1(62.23,45.72) 67.94,45.72 69.21,46.99 69.21,69.85 67.31,71.75 v1(67.31,80.01)
N_218: length 44
  TOP w0.254: v1(104.14,135.89) 104.14,136.53 ; v1(99.06,101.6) 99.06,102.87 99.33,103.14 U6.20
  CONDUCTIVE3 w0.254: v1(104.14,135.89) 104.14,127.63 106.05,125.73 106.05,102.87 104.77,101.6 v1(99.06,101.6)
N_219: length 1.7
  TOP w0.254: U6.16 99.33,105.14 98.42,106.05
N_220: length 44
  TOP w0.254: v1(25.4,101.6) 25.4,102.87 25.67,103.14 U1.20 ; v1(30.48,135.89) 30.48,136.53
  CONDUCTIVE3 w0.254: v1(25.4,101.6) 31.11,101.6 32.38,102.87 32.38,125.73 30.48,127.63 v1(30.48,135.89)
N_221: length 1.7
  TOP w0.254: U1.16 25.67,105.14 24.77,106.05
N_222: length 1.7
  TOP w0.254: 135.26,106.05 136.16,105.14 U7.16
N_223: length 1.7
  TOP w0.254: 61.6,50.17 62.5,49.26 U8.16
N_224: length 1.7
  TOP w0.254: U9.16 99.33,49.26 98.42,50.17
N_225: length 1.7
  TOP w0.254: 135.26,50.17 136.16,49.26 U10.16
N_231: length 3.7
  TOP w0.254: R125.2 30.48,15.88 28.91,17.44 28.91,17.85
N_232: length 9.6
  TOP w0.254: R127.2 25.4,15.88 26.04,16.51 26.67,16.51 27.61,17.45 27.61,17.85 ; SW1.2 25.4,11.43 R127.1
N_243: length 8.6
  TOP w0.254: IC4.11 62.62,25.15 v1(62.87,25.4)
  CONDUCTIVE2 w0.254: P23.P_1 67.31,25.4 v1(62.87,25.4)
N_244: length 6.7
  TOP w0.254: IC4.17 58.72,25.74 58.42,26.04 58.42,26.67 57.15,27.94 P24.P_1
N_251: length 2.6
  TOP w0.254: U5.14 64.27,107.45 C27.2
N_252: length 4.2
  TOP w0.254: U5.8 67.94,104.14 69.21,105.41 R133.1
N_253: length 3.7
  TOP w0.254: U5.6 68.31,103.14 68.58,102.87 C28.2
N_254: length 7.6
  TOP w0.254: 68.58,107.95 68.16,108.37 R135.1 ; 68.58,107.95 R134.2 ; 68.58,107.95 68.58,106.05 67.17,104.64 U5.9
N_255: length 23.3
  TOP w0.254: v1(67.94,125.09) 67.94,124.46 67.65,124.16 Q75.4 ; U5.13 64.77,111.76 v1(63.5,113.03)
  CONDUCTIVE3 w0.254: v1(63.5,113.03) 63.5,120.65 v1(67.94,125.09)
N_257: length 16.7
  TOP w0.254: U5.11 65.77,117.84 67.31,119.38 69.59,119.38 R137.2
N_258: length 4.5
  TOP w0.254: U5.3 C30.2 ; C30.1 R136.2
N_260: length 3.4
  TOP w0.254: U5.17 61.1,104.64 60.72,105.02 C31.2
N_261: length 7
  TOP w0.254: U5.1 63.77,101.45 R138.2 61.18,99.91 60.96,99.69 60.96,98.42 60.75,98.21 R139.1
N_266: length 2.6
  TOP w0.254: C34.2 101.1,107.45 U6.14
N_267: length 4.2
  TOP w0.254: R142.1 106.05,105.41 104.77,104.14 U6.8
N_268: length 3.7
  TOP w0.254: U6.6 105.14,103.14 105.41,102.87 C35.2
N_269: length 7.6
  TOP w0.254: R144.1 104.99,108.37 105.41,107.95 ; 105.41,107.95 105.41,106.05 104,104.64 U6.9 ; 105.41,107.95 R143.2
N_270: length 23.3
  TOP w0.254: Q76.4 104.48,124.16 104.77,124.46 v1(104.77,125.09) ; U6.13 101.6,111.76 v1(100.33,113.03)
  CONDUCTIVE3 w0.254: v1(104.77,125.09) 100.33,120.65 v1(100.33,113.03)
N_272: length 16.7
  TOP w0.254: U6.11 102.6,117.84 104.14,119.38 106.42,119.38 R146.2
N_273: length 4.5
  TOP w0.254: U6.3 C37.2 ; C37.1 R145.2
N_275: length 3.4
  TOP w0.254: U6.17 97.92,104.64 97.55,105.02 C38.2
N_276: length 7
  TOP w0.254: U6.1 100.6,101.45 R147.2 98,99.91 97.79,99.69 97.79,98.42 97.58,98.21 R148.1
N_281: length 2.6
  TOP w0.254: C41.2 137.93,107.45 U7.14
N_282: length 4.2
  TOP w0.254: U7.8 141.61,104.14 142.88,105.41 R151.1
N_283: length 3.7
  TOP w0.254: C42.2 142.24,102.87 141.97,103.14 U7.6
N_284: length 8
  TOP w0.254: 142.24,107.95 142.24,105.41 141.47,104.64 U7.9 ; 142.24,107.95 141.82,108.37 R153.1 ; 142.24,107.95 R152.2
N_285: length 23.3
  TOP w0.254: v1(141.61,125.09) 141.61,124.46 141.31,124.16 Q77.4 ; U7.13 138.43,111.76 v1(137.16,113.03)
  CONDUCTIVE3 w0.254: v1(137.16,113.03) 137.16,120.65 v1(141.61,125.09)
N_287: length 16.7
  TOP w0.254: U7.11 139.43,117.84 140.97,119.38 143.25,119.38 R155.2
N_288: length 4.5
  TOP w0.254: U7.3 C44.2 ; C44.1 R154.2
N_290: length 3.4
  TOP w0.254: C45.2 134.38,105.02 134.76,104.64 U7.17
N_291: length 7
  TOP w0.254: U7.1 137.43,101.45 R156.2 134.84,99.91 134.62,99.69 134.62,98.42 134.41,98.21 R157.1
N_292: length 44.7
  TOP w0.254: U7.20 136.16,103.14 135.89,102.87 v1(135.89,101.6) ; v1(140.97,135.89) 140.97,137.16
  CONDUCTIVE3 w0.254: v1(140.97,135.89) 140.97,127 142.88,125.09 142.88,102.87 141.61,101.6 v1(135.89,101.6)
N_296: length 2.6
  TOP w0.254: C48.2 64.27,51.57 U8.14
N_297: length 4.2
  TOP w0.254: U8.8 67.94,48.26 69.21,49.53 R160.1
N_298: length 3.7
  TOP w0.254: U8.6 68.31,47.26 68.58,46.99 C49.2
N_299: length 7.6
  TOP w0.254: U8.9 67.17,48.76 68.58,50.17 68.58,52.07 ; 68.58,52.07 R161.2 ; 68.58,52.07 68.16,52.49 R162.1
N_300: length 23.3
  TOP w0.254: Q78.4 67.65,68.28 67.94,68.58 v1(67.94,69.21) ; U8.13 64.77,55.88 v1(63.5,57.15)
  CONDUCTIVE3 w0.254: v1(63.5,57.15) 63.5,64.77 v1(67.94,69.21)
N_302: length 16.7
  TOP w0.254: U8.11 65.77,61.96 67.31,63.5 69.59,63.5 R164.2
N_303: length 4.4
  TOP w0.254: C51.1 R163.2 ; U8.3 C51.2
N_305: length 3.4
  TOP w0.254: C52.2 60.72,49.14 61.1,48.76 U8.17
N_306: length 7
  TOP w0.254: U8.1 63.77,45.57 R165.2 61.18,44.03 60.96,43.82 60.96,42.55 60.75,42.33 R166.1
N_311: length 2.6
  TOP w0.254: U9.14 101.1,51.57 C55.2
N_312: length 4.2
  TOP w0.254: U9.8 104.77,48.26 106.05,49.53 R169.1
N_313: length 3.7
  TOP w0.254: U9.6 105.14,47.26 105.41,46.99 C56.2
N_314: length 7.6
  TOP w0.254: R171.1 104.99,52.49 105.41,52.07 ; 105.41,52.07 R170.2 ; 105.41,52.07 105.41,50.17 104,48.76 U9.9
N_315: length 23.3
  TOP w0.254: v1(104.77,69.21) 104.77,68.58 104.48,68.28 Q79.4 ; U9.13 101.6,55.88 v1(100.33,57.15)
  CONDUCTIVE3 w0.254: v1(100.33,57.15) 100.33,64.77 v1(104.77,69.21)
N_317: length 16.7
  TOP w0.254: R173.2 106.42,63.5 104.14,63.5 102.6,61.96 U9.11
N_318: length 4.4
  TOP w0.254: U9.3 C58.2 ; C58.1 R172.2
N_320: length 3.4
  TOP w0.254: U9.17 97.92,48.76 97.55,49.14 C59.2
N_321: length 7
  TOP w0.254: U9.1 100.6,45.57 R174.2 98,44.03 97.79,43.82 97.79,42.55 97.58,42.33 R175.1
N_326: length 2.6
  TOP w0.254: C62.2 137.93,51.57 U10.14
N_327: length 4.2
  TOP w0.254: U10.8 142.24,48.26 143.51,49.53 R178.1
N_328: length 3.7
  TOP w0.254: U10.6 141.34,47.26 141.61,46.99 C63.2
N_329: length 8
  TOP w0.254: 142.24,52.07 142.24,49.53 141.47,48.76 U10.9 ; 142.24,52.07 R179.2 ; 142.24,52.07 141.82,52.49 R180.1
N_330: length 23.3
  TOP w0.254: U10.13 138.43,55.88 v1(137.16,57.15) ; v1(141.61,69.21) 141.61,68.58 141.31,68.28 Q80.4
  CONDUCTIVE3 w0.254: v1(137.16,57.15) 137.16,64.77 v1(141.61,69.21)
N_332: length 16.7
  TOP w0.254: R182.2 143.25,63.5 140.97,63.5 139.43,61.96 U10.11
N_333: length 4.4
  TOP w0.254: C65.1 R181.2 ; U10.3 C65.2
N_335: length 3.4
  TOP w0.254: C66.2 134.38,49.14 134.76,48.76 U10.17
N_336: length 7.1
  TOP w0.254: U10.1 137.43,45.36 136.11,44.03 R183.2 134.84,44.03 134.62,43.82 134.62,42.55 134.41,42.33 R184.1
PWMDIM1: length 45
  TOP w0.254: U1.10 29.78,105.98 v1(30.48,106.68)
  CONDUCTIVE2 w0.254: CON10.1 14.22,74.93 27.43,88.14 27.43,98.3 30.48,101.35 v1(30.48,106.68)
PWMDIM2: length 100.1
  TOP w0.254: v1(67.31,106.68) 66.61,105.98 U5.10
  CONDUCTIVE2 w0.254: v1(67.31,106.68) v1(67.31,86.61)
  CONDUCTIVE3 w0.254: CON10.6 5.84,69.25 5.84,65.53 8.13,63.25 36.58,63.25 59.94,86.61 v1(67.31,86.61)
PWMDIM3: length 124.5
  TOP w0.254: U6.10 103.44,105.98 v1(104.14,106.68)
  CONDUCTIVE2 w0.254: v1(104.14,106.68) v1(104.14,91.44)
  CONDUCTIVE3 w0.254: CON10.2 9.81,77.22 22.86,77.22 27.69,72.39 41.4,72.39 57.66,88.65 101.35,88.65 v1(104.14,91.44)
PWMDIM4: length 208.1
  TOP w0.254: U7.10 140.27,105.98 v1(140.97,106.68)
  CONDUCTIVE2 w0.254: v1(140.97,106.68) 140.97,92.71 136.4,88.14 128.52,88.14 122.68,82.3 85.85,82.3 76.45,72.9 76.45,44.45 68.83,36.83 32,36.83 27.18,41.66 27.18,54.86 13.11,68.93 CON10.7
PWMDIM5: length 93.7
  TOP w0.254: v1(67.31,50.8) 66.61,50.1 U8.10
  CONDUCTIVE2 w0.254: CON10.3 13.94,72.93 28.45,58.42 28.45,42.16 32.26,38.35 63.5,38.35 67.31,42.16 v1(67.31,50.8)
PWMDIM6: length 135.5
  TOP w0.254: v1(104.14,50.8) 103.44,50.1 U9.10
  CONDUCTIVE2 w0.254: CON10.8 6.7,68.93 5.84,68.07 5.84,64.26 9.65,60.45 17.27,60.45 25.91,51.82 25.91,41.15 31.75,35.31 97.03,35.31 104.14,42.42 v1(104.14,50.8)
PWMDIM7: length 180.1
  TOP w0.254: U10.10 140.27,50.1 v1(140.97,50.8)
  CONDUCTIVE2 w0.254: CON10.4 5.84,72.93 4.32,71.41 4.32,61.72 8.13,57.91 16,57.91 24.89,49.02 24.89,40.39 31.5,33.78 131.57,33.78 140.97,43.18 v1(140.97,50.8)

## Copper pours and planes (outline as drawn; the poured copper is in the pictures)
+5V on TOP: 62.3,5.71 62.25,5.74 62.23,5.79 62.23,15.16 62.25,15.22 62.3,15.24 76.2,15.24 77.72,16.76 77.72,26.34 77.75,26.39 77.8,26.42 79.68,26.42 79.73,26.39 79.76,26.34 79.76,5.79 79.73,5.74 79.68,5.71
+12V on TOP: 13.97,31.75 13.97,47.62 24.13,47.62 24.13,31.75
+12V on TOP: 38.74,5.71 38.74,15.88 52.71,15.88 52.71,5.71
GND on TOP: 0.4,151.93 0.42,151.98 0.47,152 151.93,152 151.98,151.98 152,151.93 152,0.47 151.98,0.42 151.93,0.4 0.47,0.4 0.42,0.42 0.4,0.47 ; 42 cut-outs
GND on BOTTOM: 0.4,151.93 0.42,151.98 0.47,152 151.93,152 151.98,151.98 152,151.93 152,0.47 151.98,0.42 151.93,0.4 0.47,0.4 0.42,0.42 0.4,0.47 ; 274 cut-outs
VCC on TOP: 38.1,93.98 38.1,117.47 62.23,117.47 62.23,107.95 60.96,107.95 60.96,110.49 41.91,110.49 41.91,93.98
VCC on TOP: 111.76,93.98 111.76,117.47 135.89,117.47 135.89,107.95 134.62,107.95 134.62,110.49 115.57,110.49 115.57,93.98
VCC on TOP: 74.93,93.98 74.93,117.47 99.06,117.47 99.06,107.95 97.79,107.95 97.79,110.49 78.74,110.49 78.74,93.98
VCC on TOP: 2.54,93.98 2.54,117.47 25.4,117.47 25.4,107.95 24.13,107.95 24.13,110.49 5.71,110.49 5.71,93.98
VCC on TOP: 31.75,31.75 31.75,83.82 41.28,83.82 41.28,61.6 62.23,61.6 62.23,52.07 60.96,52.07 60.96,54.61 41.28,54.61 41.28,36.83 74.93,36.83 74.93,61.6 99.06,61.6 99.06,52.07 97.79,52.07 97.79,54.61 78.74,54.61 78.74,36.83 111.76,36.83 111.76,61.6 135.89,61.6 135.89,52.07 134.62,52.07 134.62,54.61 115.57,54.61 115.57,31.75
VCC on CONDUCTIVE3: 115.57,94.05 115.55,94 115.5,93.98 41.28,93.98 41.28,74.93 31.75,74.93 31.75,93.98 2.61,93.98 2.56,94 2.54,94.05 2.54,98.99 2.56,99.04 2.61,99.06 115.5,99.06 115.55,99.04 115.57,98.99 ; 3 cut-outs
LED+1 on TOP: 15.88,132.08 15.88,143.51 19.68,143.51 19.68,132.08
LED+2 on TOP: 52.71,132.08 52.71,143.51 56.52,143.51 56.52,132.08
LED+3 on TOP: 89.53,132.08 89.53,143.51 93.34,143.51 93.34,132.08
LED+4 on TOP: 126.36,132.08 126.36,143.51 130.18,143.51 130.18,132.08
LED+5 on TOP: 52.71,76.2 52.71,87.63 56.52,87.63 56.52,76.2
LED+6 on TOP: 89.53,76.2 89.53,87.63 93.34,87.63 93.34,76.2
LED+7 on TOP: 126.36,76.2 126.36,87.63 130.18,87.63 130.18,76.2
LED-1 on TOP: 24.77,139.38 24.77,143.51 28.57,143.51 28.57,139.38
LED-2 on TOP: 61.6,139.38 61.6,143.51 65.41,143.51 65.41,139.38
LED-3 on TOP: 98.42,139.38 98.42,143.51 102.23,143.51 102.23,139.38
LED-4 on TOP: 135.26,139.38 135.26,143.51 139.06,143.51 139.06,139.38
LED-5 on TOP: 61.6,83.5 61.6,87.63 65.41,87.63 65.41,83.5
LED-6 on TOP: 98.42,83.5 98.42,87.63 102.23,87.63 102.23,83.5
LED-7 on TOP: 135.26,83.5 135.26,87.63 139.06,87.63 139.06,83.5
LV1 on TOP: 21.59,100.96 21.59,102.23 24.13,102.23 24.13,100.96
LV1 on TOP: 6.35,108.58 6.35,109.85 13.97,109.85 13.97,108.58
LV1 on TOP: 31.11,125.73 31.11,133.99 36.83,133.99 36.83,125.73
LV1 on CONDUCTIVE2: 6.43,96.52 6.37,96.54 6.35,96.59 6.35,129.47 6.37,129.52 6.43,129.54 31.11,129.54 31.11,133.91 31.14,133.96 31.19,133.99 36.76,133.99 36.81,133.96 36.83,133.91 36.83,125.8 36.81,125.75 36.76,125.73 13.97,125.73 13.97,102.23 19.55,102.23 19.63,102.17 19.57,102.09 19.68,101.1 19.8,102.09 19.74,102.17 19.82,102.23 24.05,102.23 24.11,102.21 24.13,102.16 24.13,96.59 24.11,96.54 24.05,96.52
LV2 on TOP: 58.42,100.96 58.42,102.23 60.96,102.23 60.96,100.96
LV2 on TOP: 43.18,108.58 43.18,109.85 50.8,109.85 50.8,108.58
LV2 on TOP: 67.94,125.73 67.94,133.99 73.66,133.99 73.66,125.73
LV2 on CONDUCTIVE2: 43.26,96.52 43.2,96.54 43.18,96.59 43.18,129.47 43.2,129.52 43.26,129.54 67.94,129.54 67.94,133.91 67.97,133.96 68.02,133.99 73.58,133.99 73.64,133.96 73.66,133.91 73.66,125.8 73.64,125.75 73.58,125.73 50.8,125.73 50.8,102.23 56.38,102.23 56.46,102.17 56.4,102.09 56.52,101.1 56.63,102.09 56.57,102.17 56.65,102.23 60.89,102.23 60.94,102.21 60.96,102.16 60.96,96.59 60.94,96.54 60.89,96.52
LV3 on TOP: 95.25,100.96 95.25,102.23 97.79,102.23 97.79,100.96
LV3 on TOP: 80.01,108.58 80.01,109.85 87.63,109.85 87.63,108.58
LV3 on TOP: 104.77,125.73 104.77,133.99 110.49,133.99 110.49,125.73
LV3 on CONDUCTIVE2: 80.08,96.52 80.03,96.54 80.01,96.59 80.01,129.47 80.03,129.52 80.08,129.54 104.77,129.54 104.77,133.91 104.8,133.96 104.85,133.99 110.41,133.99 110.47,133.96 110.49,133.91 110.49,125.8 110.47,125.75 110.41,125.73 87.63,125.73 87.63,102.23 93.21,102.23 93.29,102.17 93.23,102.09 93.34,101.1 93.46,102.09 93.4,102.17 93.48,102.23 97.71,102.23 97.77,102.21 97.79,102.16 97.79,96.59 97.77,96.54 97.71,96.52
LV4 on TOP: 141.61,125.73 141.61,133.99 147.32,133.99 147.32,125.73
LV4 on TOP: 132.08,100.96 132.08,102.23 134.62,102.23 134.62,100.96
LV4 on TOP: 116.84,108.58 116.84,109.85 124.46,109.85 124.46,108.58
LV4 on CONDUCTIVE2: 116.91,96.52 116.86,96.54 116.84,96.59 116.84,129.47 116.86,129.52 116.91,129.54 141.61,129.54 141.61,133.91 141.63,133.96 141.68,133.99 147.25,133.99 147.3,133.96 147.32,133.91 147.32,125.8 147.3,125.75 147.25,125.73 124.46,125.73 124.46,102.23 130.04,102.23 130.12,102.17 130.06,102.09 130.18,101.1 130.29,102.09 130.23,102.17 130.31,102.23 134.55,102.23 134.6,102.21 134.62,102.16 134.62,96.59 134.6,96.54 134.55,96.52
LV5 on TOP: 58.42,45.09 58.42,46.36 60.96,46.36 60.96,45.09
LV5 on TOP: 67.94,69.85 67.94,78.1 73.66,78.1 73.66,69.85
LV5 on TOP: 43.18,52.71 43.18,53.98 50.8,53.98 50.8,52.71
LV5 on CONDUCTIVE2: 43.26,40.64 43.2,40.66 43.18,40.72 43.18,73.58 43.2,73.64 43.26,73.66 67.94,73.66 67.94,78.03 67.97,78.08 68.02,78.1 73.58,78.1 73.64,78.08 73.66,78.03 73.66,69.92 73.64,69.87 73.58,69.85 50.8,69.85 50.8,46.36 56.38,46.36 56.46,46.29 56.4,46.21 56.52,45.22 56.63,46.21 56.57,46.29 56.65,46.36 60.89,46.36 60.94,46.33 60.96,46.28 60.96,40.72 60.94,40.66 60.89,40.64
LV6 on TOP: 95.25,45.09 95.25,46.36 97.79,46.36 97.79,45.09
LV6 on TOP: 80.01,52.71 80.01,53.98 87.63,53.98 87.63,52.71
